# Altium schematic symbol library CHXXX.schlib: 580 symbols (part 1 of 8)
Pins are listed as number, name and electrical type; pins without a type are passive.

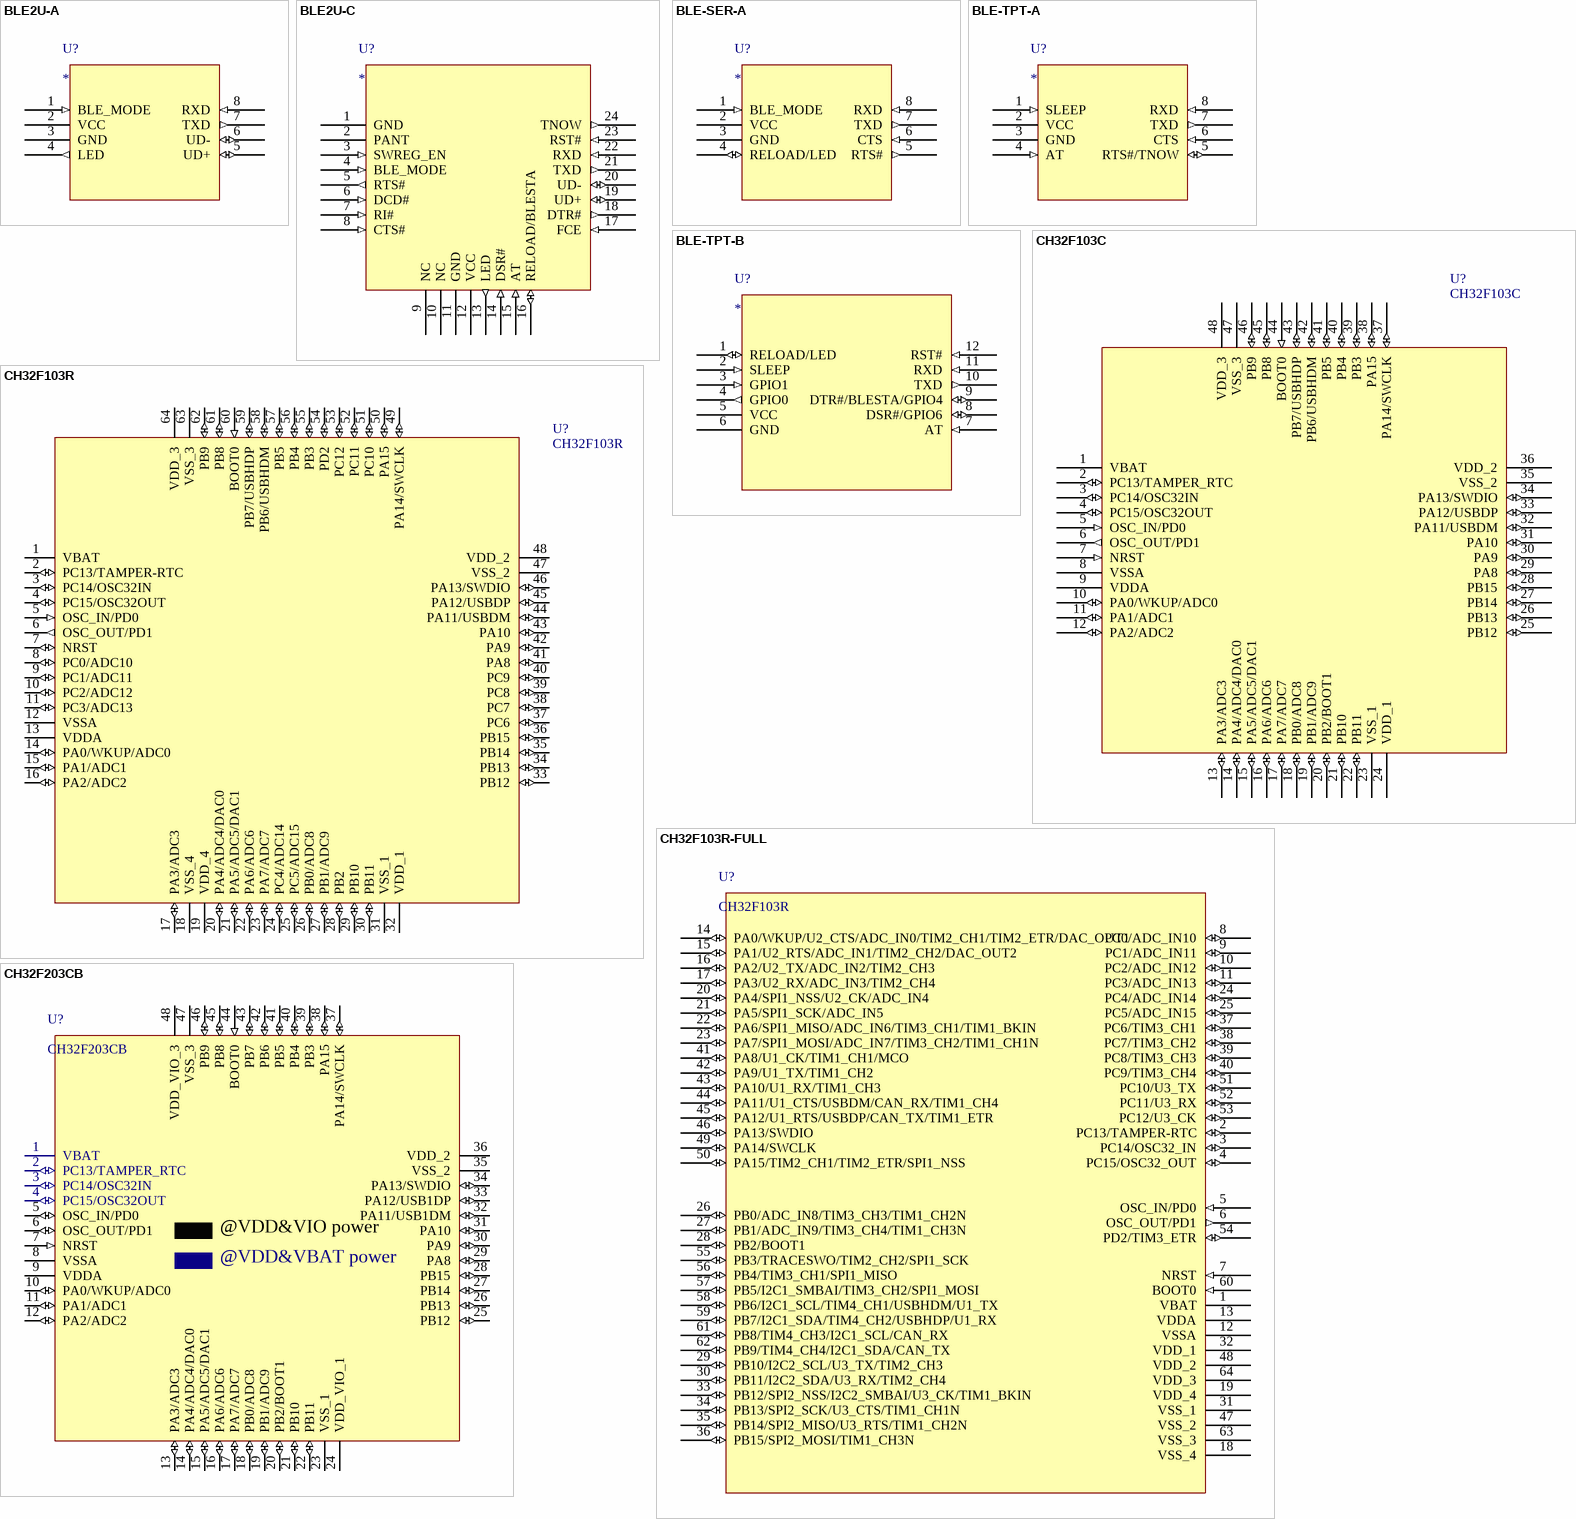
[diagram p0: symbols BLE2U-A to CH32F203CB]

## BLE2U-A
designator U?
BLE/UART/USB transparent transmission module, 8 pins
footprint BLEMOD-R1-1v1-8PIN
pins: 1 BLE_MODE (in), 2 VCC (power), 3 GND (power), 4 LED (out), 5 UD+ (io), 6 UD- (io), 7 TXD (out), 8 RXD (in)

## BLE2U-C
designator U?
BLE/UART/USB transparent transmission module, 24 pins
footprint BLEMOD-R2-1v0-24PIN
pins: 1 GND (power), 2 PANT, 3 SWREG_EN (in), 4 BLE_MODE (in), 5 RTS# (out), 6 DCD# (in), 7 RI# (in), 8 CTS# (in), 9 NC, 10 NC, 11 GND (power), 12 VCC (power), 13 LED (out), 14 DSR# (in), 15 AT (in), 16 RELOAD/BLESTA   (io), 17 FCE (in), 18 DTR# (out), 19 UD+ (io), 20 UD- (io), 21 TXD (out), 22 RXD (in), 23 RST# (in), 24 TNOW (out)

## BLE-SER-A
designator U?
BLE to UART / TTL Serial module, 8 pins
footprint BLEMOD-R1-1v1-8PIN
pins: 1 BLE_MODE (in), 2 VCC (power), 3 GND (power), 4 RELOAD/LED (io), 5 RTS# (out), 6 CTS (in), 7 TXD (out), 8 RXD (in)

## BLE-TPT-A
designator U?
BLE/UART transparent transmission module, 8 pins
footprint BLEMOD-R1-1v1-8PIN
pins: 1 SLEEP (in), 2 VCC (power), 3 GND (power), 4 AT (in), 5 RTS#/TNOW (io), 6 CTS (in), 7 TXD (out), 8 RXD (in)

## BLE-TPT-B
designator U?
BLE/UART transparent transmission module, 12 pins
footprint BLEMOD-R0-1v0-12PIN
pins: 1 RELOAD/LED (io), 2 SLEEP (in), 3 GPIO1 (in), 4 GPIO0 (out), 5 VCC (power), 6 GND (power), 7 AT (in), 8 DSR#/GPIO6 (io), 9 DTR#/BLESTA/GPIO4 (io), 10 TXD (out), 11 RXD (in), 12 RST# (in)

## CH32F103C
designator U?
ARM M3 MCU with USB device & USB host & ADC & 12bit DAC & Touch Key & CAN
footprint LQFP48
footprint QFN48_7X7 (Footprint not found)
pins: 1 VBAT (power), 2 PC13/TAMPER_RTC (io), 3 PC14/OSC32IN (io), 4 PC15/OSC32OUT (io), 5 OSC_IN/PD0 (in), 6 OSC_OUT/PD1 (out), 7 NRST (in), 8 VSSA (power), 9 VDDA (power), 10 PA0/WKUP/ADC0 (io), 11 PA1/ADC1 (io), 12 PA2/ADC2 (io), 13 PA3/ADC3 (io), 14 PA4/ADC4/DAC0 (io), 15 PA5/ADC5/DAC1 (io), 16 PA6/ADC6 (io), 17 PA7/ADC7 (io), 18 PB0/ADC8 (io), 19 PB1/ADC9 (io), 20 PB2/BOOT1 (io), 21 PB10 (io), 22 PB11 (io), 23 VSS_1 (power), 24 VDD_1 (power), 25 PB12 (io), 26 PB13 (io), 27 PB14 (io), 28 PB15 (io), 29 PA8 (io), 30 PA9 (io), 31 PA10 (io), 32 PA11/USBDM (io), 33 PA12/USBDP (io), 34 PA13/SWDIO (io), 35 VSS_2 (power), 36 VDD_2 (power), 37 PA14/SWCLK (io), 38 PA15 (io), 39 PB3 (io), 40 PB4 (io), 41 PB5 (io), 42 PB6/USBHDM (io), 43 PB7/USBHDP (io), 44 BOOT0 (in), 45 PB8 (io), 46 PB9 (io), 47 VSS_3 (power), 48 VDD_3 (power)

## CH32F103R
designator U?
ARM M3 MCU with USB device & USB host & ADC & 12bit DAC & Touch Key & CAN
footprint LQFP64M_10X10
pins: 1 VBAT (power), 2 PC13/TAMPER-RTC (io), 3 PC14/OSC32IN (io), 4 PC15/OSC32OUT (io), 5 OSC_IN/PD0 (in), 6 OSC_OUT/PD1 (out), 7 NRST (io), 8 PC0/ADC10 (io), 9 PC1/ADC11 (io), 10 PC2/ADC12 (io), 11 PC3/ADC13 (io), 12 VSSA (power), 13 VDDA (power), 14 PA0/WKUP/ADC0 (io), 15 PA1/ADC1 (io), 16 PA2/ADC2 (io), 17 PA3/ADC3 (io), 18 VSS_4 (power), 19 VDD_4 (power), 20 PA4/ADC4/DAC0 (io), 21 PA5/ADC5/DAC1 (io), 22 PA6/ADC6 (io), 23 PA7/ADC7 (io), 24 PC4/ADC14 (io), 25 PC5/ADC15 (io), 26 PB0/ADC8 (io), 27 PB1/ADC9 (io), 28 PB2 (io), 29 PB10 (io), 30 PB11 (io), 31 VSS_1 (power), 32 VDD_1 (power), 33 PB12 (io), 34 PB13 (io), 35 PB14 (io), 36 PB15 (io), 37 PC6 (io), 38 PC7 (io), 39 PC8 (io), 40 PC9 (io), 41 PA8 (io), 42 PA9 (io), 43 PA10 (io), 44 PA11/USBDM (io), 45 PA12/USBDP (io), 46 PA13/SWDIO (io), 47 VSS_2 (power), 48 VDD_2 (power), 49 PA14/SWCLK (io), 50 PA15 (io), 51 PC10 (io), 52 PC11 (io), 53 PC12 (io), 54 PD2 (io), 55 PB3 (io), 56 PB4 (io), 57 PB5 (io), 58 PB6/USBHDM (io), 59 PB7/USBHDP (io), 60 BOOT0 (in), 61 PB8 (io), 62 PB9 (io), 63 VSS_3 (power), 64 VDD_3 (power)

## CH32F103R-FULL
designator U?, comment CH32F103R
ARM M3 MCU with USB device & USB host & ADC & 12bit DAC & Touch Key & CAN
footprint LQFP64M_10X10 (Footprint not found)
pins: 1 VBAT (power), 2 PC13/TAMPER-RTC (io), 3 PC14/OSC32_IN (io), 4 PC15/OSC32_OUT (io), 5 OSC_IN/PD0 (in), 6 OSC_OUT/PD1 (out), 7 NRST (in), 8 PC0/ADC_IN10 (io), 9 PC1/ADC_IN11 (io), 10 PC2/ADC_IN12 (io), 11 PC3/ADC_IN13 (io), 12 VSSA (power), 13 VDDA (power), 14 PA0/WKUP/U2_CTS/ADC_IN0/TIM2_CH1/TIM2_ETR/DAC_OUT1 (io), 15 PA1/U2_RTS/ADC_IN1/TIM2_CH2/DAC_OUT2 (io), 16 PA2/U2_TX/ADC_IN2/TIM2_CH3 (io), 17 PA3/U2_RX/ADC_IN3/TIM2_CH4 (io), 18 VSS_4 (power), 19 VDD_4 (power), 20 PA4/SPI1_NSS/U2_CK/ADC_IN4 (io), 21 PA5/SPI1_SCK/ADC_IN5 (io), 22 PA6/SPI1_MISO/ADC_IN6/TIM3_CH1/TIM1_BKIN (io), 23 PA7/SPI1_MOSI/ADC_IN7/TIM3_CH2/TIM1_CH1N (io), 24 PC4/ADC_IN14 (io), 25 PC5/ADC_IN15 (io), 26 PB0/ADC_IN8/TIM3_CH3/TIM1_CH2N (io), 27 PB1/ADC_IN9/TIM3_CH4/TIM1_CH3N (io), 28 PB2/BOOT1 (io), 29 PB10/I2C2_SCL/U3_TX/TIM2_CH3 (io), 30 PB11/I2C2_SDA/U3_RX/TIM2_CH4 (io), 31 VSS_1 (power), 32 VDD_1 (power), 33 PB12/SPI2_NSS/I2C2_SMBAI/U3_CK/TIM1_BKIN (io), 34 PB13/SPI2_SCK/U3_CTS/TIM1_CH1N  (io), 35 PB14/SPI2_MISO/U3_RTS/TIM1_CH2N (io), 36 PB15/SPI2_MOSI/TIM1_CH3N (io), 37 PC6/TIM3_CH1 (io), 38 PC7/TIM3_CH2 (io), 39 PC8/TIM3_CH3 (io), 40 PC9/TIM3_CH4 (io), 41 PA8/U1_CK/TIM1_CH1/MCO (io), 42 PA9/U1_TX/TIM1_CH2 (io), 43 PA10/U1_RX/TIM1_CH3 (io), 44 PA11/U1_CTS/USBDM/CAN_RX/TIM1_CH4 (io), 45 PA12/U1_RTS/USBDP/CAN_TX/TIM1_ETR (io), 46 PA13/SWDIO (io), 47 VSS_2 (power), 48 VDD_2 (power), 49 PA14/SWCLK (io), 50 PA15/TIM2_CH1/TIM2_ETR/SPI1_NSS (io), 51 PC10/U3_TX (io), 52 PC11/U3_RX (io), 53 PC12/U3_CK (io), 54 PD2/TIM3_ETR (io), 55 PB3/TRACESWO/TIM2_CH2/SPI1_SCK (io), 56 PB4/TIM3_CH1/SPI1_MISO (io), 57 PB5/I2C1_SMBAI/TIM3_CH2/SPI1_MOSI (io), 58 PB6/I2C1_SCL/TIM4_CH1/USBHDM/U1_TX (io), 59 PB7/I2C1_SDA/TIM4_CH2/USBHDP/U1_RX (io), 60 BOOT0 (in), 61 PB8/TIM4_CH3/I2C1_SCL/CAN_RX (io), 62 PB9/TIM4_CH4/I2C1_SDA/CAN_TX (io), 63 VSS_3 (power), 64 VDD_3 (power)

## CH32F203CB
designator U?
ARM M3 HD-MCU, 144MHz, 8*UART, 10*Timer, 4*OPA
footprint LQFP48
pins: 1 VBAT (power), 2 PC13/TAMPER_RTC (io), 3 PC14/OSC32IN (io), 4 PC15/OSC32OUT (io), 5 OSC_IN/PD0 (io), 6 OSC_OUT/PD1 (io), 7 NRST (in), 8 VSSA (power), 9 VDDA (power), 10 PA0/WKUP/ADC0 (io), 11 PA1/ADC1 (io), 12 PA2/ADC2 (io), 13 PA3/ADC3 (io), 14 PA4/ADC4/DAC0 (io), 15 PA5/ADC5/DAC1 (io), 16 PA6/ADC6 (io), 17 PA7/ADC7 (io), 18 PB0/ADC8 (io), 19 PB1/ADC9 (io), 20 PB2/BOOT1 (io), 21 PB10 (io), 22 PB11 (io), 23 VSS_1 (power), 24 VDD_VIO_1 (power), 25 PB12 (io), 26 PB13 (io), 27 PB14 (io), 28 PB15 (io), 29 PA8 (io), 30 PA9 (io), 31 PA10 (io), 32 PA11/USB1DM (io), 33 PA12/USB1DP (io), 34 PA13/SWDIO (io), 35 VSS_2 (power), 36 VDD_2 (power), 37 PA14/SWCLK (io), 38 PA15 (io), 39 PB3 (io), 40 PB4 (io), 41 PB5 (io), 42 PB6 (io), 43 PB7 (io), 44 BOOT0 (in), 45 PB8 (io), 46 PB9 (io), 47 VSS_3 (power), 48 VDD_VIO_3 (power)

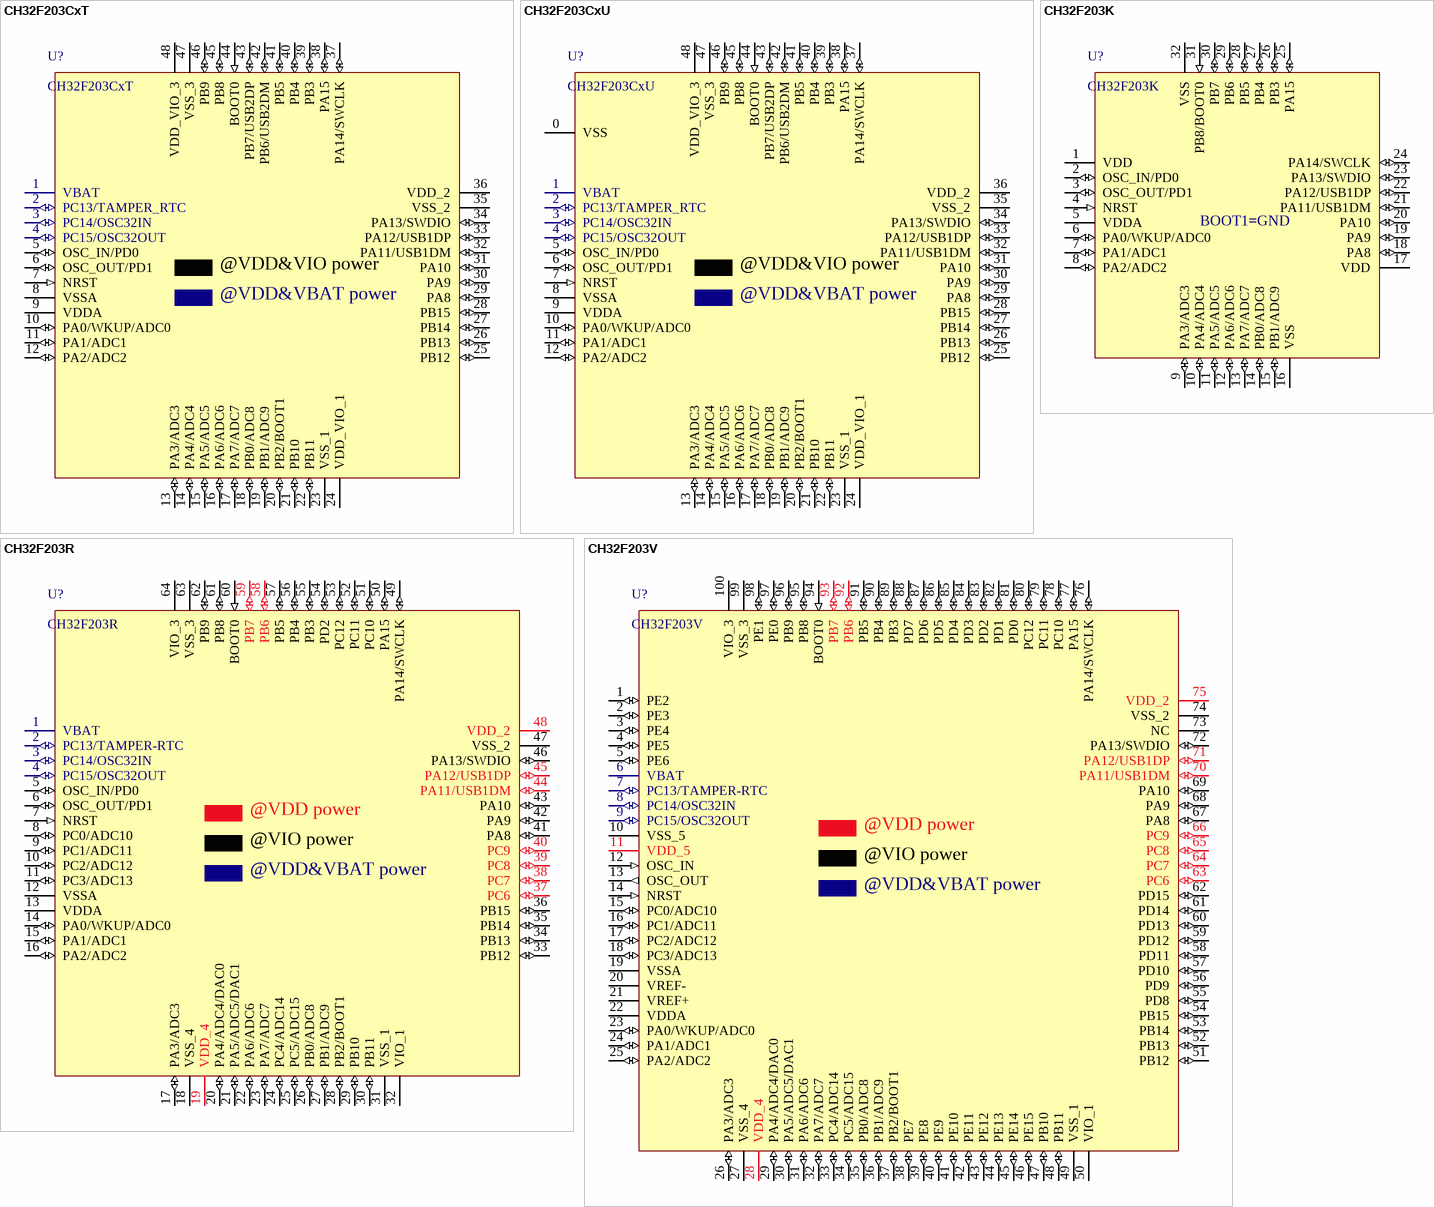
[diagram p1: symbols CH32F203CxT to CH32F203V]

## CH32F203CxT
designator U?
ARM M3 LMD-MCU, 144MHz, 2*USB FS, CAN
footprint LQFP48
pins: 1 VBAT (power), 2 PC13/TAMPER_RTC (io), 3 PC14/OSC32IN (io), 4 PC15/OSC32OUT (io), 5 OSC_IN/PD0 (io), 6 OSC_OUT/PD1 (io), 7 NRST (in), 8 VSSA (power), 9 VDDA (power), 10 PA0/WKUP/ADC0 (io), 11 PA1/ADC1 (io), 12 PA2/ADC2 (io), 13 PA3/ADC3 (io), 14 PA4/ADC4 (io), 15 PA5/ADC5 (io), 16 PA6/ADC6 (io), 17 PA7/ADC7 (io), 18 PB0/ADC8 (io), 19 PB1/ADC9 (io), 20 PB2/BOOT1 (io), 21 PB10 (io), 22 PB11 (io), 23 VSS_1 (power), 24 VDD_VIO_1 (power), 25 PB12 (io), 26 PB13 (io), 27 PB14 (io), 28 PB15 (io), 29 PA8 (io), 30 PA9 (io), 31 PA10 (io), 32 PA11/USB1DM (io), 33 PA12/USB1DP (io), 34 PA13/SWDIO (io), 35 VSS_2 (power), 36 VDD_2 (power), 37 PA14/SWCLK (io), 38 PA15 (io), 39 PB3 (io), 40 PB4 (io), 41 PB5 (io), 42 PB6/USB2DM (io), 43 PB7/USB2DP (io), 44 BOOT0 (in), 45 PB8 (io), 46 PB9 (io), 47 VSS_3 (power), 48 VDD_VIO_3 (power)

## CH32F203CxU
designator U?
ARM M3 LMD-MCU, 144MHz, 2*USB FS, CAN
footprint QFN48_7X7 (Footprint not found)
pins: 0 VSS (power), 1 VBAT (power), 2 PC13/TAMPER_RTC (io), 3 PC14/OSC32IN (io), 4 PC15/OSC32OUT (io), 5 OSC_IN/PD0 (io), 6 OSC_OUT/PD1 (io), 7 NRST (in), 8 VSSA (power), 9 VDDA (power), 10 PA0/WKUP/ADC0 (io), 11 PA1/ADC1 (io), 12 PA2/ADC2 (io), 13 PA3/ADC3 (io), 14 PA4/ADC4 (io), 15 PA5/ADC5 (io), 16 PA6/ADC6 (io), 17 PA7/ADC7 (io), 18 PB0/ADC8 (io), 19 PB1/ADC9 (io), 20 PB2/BOOT1 (io), 21 PB10 (io), 22 PB11 (io), 23 VSS_1 (power), 24 VDD_VIO_1 (power), 25 PB12 (io), 26 PB13 (io), 27 PB14 (io), 28 PB15 (io), 29 PA8 (io), 30 PA9 (io), 31 PA10 (io), 32 PA11/USB1DM (io), 33 PA12/USB1DP (io), 34 PA13/SWDIO (io), 35 VSS_2 (power), 36 VDD_2 (power), 37 PA14/SWCLK (io), 38 PA15 (io), 39 PB3 (io), 40 PB4 (io), 41 PB5 (io), 42 PB6/USB2DM (io), 43 PB7/USB2DP (io), 44 BOOT0 (in), 45 PB8 (io), 46 PB9 (io), 47 VSS_3 (power), 48 VDD_VIO_3 (power)

## CH32F203K
designator U?
ARM M3 LMD-MCU, 144MHz, USB FS, CAN
footprint LQFP32
pins: 1 VDD (power), 2 OSC_IN/PD0 (io), 3 OSC_OUT/PD1 (io), 4 NRST (in), 5 VDDA (power), 6 PA0/WKUP/ADC0 (io), 7 PA1/ADC1 (io), 8 PA2/ADC2 (io), 9 PA3/ADC3 (io), 10 PA4/ADC4 (io), 11 PA5/ADC5 (io), 12 PA6/ADC6 (io), 13 PA7/ADC7 (io), 14 PB0/ADC8 (io), 15 PB1/ADC9 (io), 16 VSS (power), 17 VDD (power), 18 PA8 (io), 19 PA9 (io), 20 PA10 (io), 21 PA11/USB1DM (io), 22 PA12/USB1DP (io), 23 PA13/SWDIO (io), 24 PA14/SWCLK (io), 25 PA15 (io), 26 PB3 (io), 27 PB4 (io), 28 PB5 (io), 29 PB6 (io), 30 PB7 (io), 31 PB8/BOOT0 (in), 32 VSS (power)

## CH32F203R
designator U?
ARM M3 HD-MCU, 144MHz, 8*UART, 10*Timer, 4*OPA
footprint LQFP64M_10X10
pins: 1 VBAT (power), 2 PC13/TAMPER-RTC (io), 3 PC14/OSC32IN (io), 4 PC15/OSC32OUT (io), 5 OSC_IN/PD0 (io), 6 OSC_OUT/PD1 (io), 7 NRST (in), 8 PC0/ADC10 (io), 9 PC1/ADC11 (io), 10 PC2/ADC12 (io), 11 PC3/ADC13 (io), 12 VSSA (power), 13 VDDA (power), 14 PA0/WKUP/ADC0 (io), 15 PA1/ADC1 (io), 16 PA2/ADC2 (io), 17 PA3/ADC3 (io), 18 VSS_4 (power), 19 VDD_4 (power), 20 PA4/ADC4/DAC0 (io), 21 PA5/ADC5/DAC1 (io), 22 PA6/ADC6 (io), 23 PA7/ADC7 (io), 24 PC4/ADC14 (io), 25 PC5/ADC15 (io), 26 PB0/ADC8 (io), 27 PB1/ADC9 (io), 28 PB2/BOOT1 (io), 29 PB10 (io), 30 PB11 (io), 31 VSS_1 (power), 32 VIO_1 (power), 33 PB12 (io), 34 PB13 (io), 35 PB14 (io), 36 PB15 (io), 37 PC6 (io), 38 PC7 (io), 39 PC8 (io), 40 PC9 (io), 41 PA8 (io), 42 PA9 (io), 43 PA10 (io), 44 PA11/USB1DM (io), 45 PA12/USB1DP (io), 46 PA13/SWDIO (io), 47 VSS_2 (power), 48 VDD_2 (power), 49 PA14/SWCLK (io), 50 PA15 (io), 51 PC10 (io), 52 PC11 (io), 53 PC12 (io), 54 PD2 (io), 55 PB3 (io), 56 PB4 (io), 57 PB5 (io), 58 PB6 (io), 59 PB7 (io), 60 BOOT0 (in), 61 PB8 (io), 62 PB9 (io), 63 VSS_3 (power), 64 VIO_3 (power)

## CH32F203V
designator U?
ARM M3 HD-MCU, 144MHz, 8*UART, 10*Timer, 4*OPA
footprint LQFP100
pins: 1 PE2 (io), 2 PE3 (io), 3 PE4 (io), 4 PE5 (io), 5 PE6 (io), 6 VBAT (power), 7 PC13/TAMPER-RTC (io), 8 PC14/OSC32IN (io), 9 PC15/OSC32OUT (io), 10 VSS_5 (power), 11 VDD_5 (power), 12 OSC_IN (in), 13 OSC_OUT (out), 14 NRST (in), 15 PC0/ADC10 (io), 16 PC1/ADC11 (io), 17 PC2/ADC12 (io), 18 PC3/ADC13 (io), 19 VSSA (power), 20 VREF- (power), 21 VREF+ (power), 22 VDDA (power), 23 PA0/WKUP/ADC0 (io), 24 PA1/ADC1 (io), 25 PA2/ADC2 (io), 26 PA3/ADC3 (io), 27 VSS_4 (power), 28 VDD_4 (power), 29 PA4/ADC4/DAC0 (io), 30 PA5/ADC5/DAC1 (io), 31 PA6/ADC6 (io), 32 PA7/ADC7 (io), 33 PC4/ADC14 (io), 34 PC5/ADC15 (io), 35 PB0/ADC8 (io), 36 PB1/ADC9 (io), 37 PB2/BOOT1 (io), 38 PE7 (io), 39 PE8 (io), 40 PE9 (io), 41 PE10 (io), 42 PE11 (io), 43 PE12 (io), 44 PE13 (io), 45 PE14 (io), 46 PE15 (io), 47 PB10 (io), 48 PB11 (io), 49 VSS_1 (power), 50 VIO_1 (power), 51 PB12 (io), 52 PB13 (io), 53 PB14 (io), 54 PB15 (io), 55 PD8 (io), 56 PD9 (io), 57 PD10 (io), 58 PD11 (io), 59 PD12 (io), 60 PD13 (io), 61 PD14 (io), 62 PD15 (io), 63 PC6 (io), 64 PC7 (io), 65 PC8 (io), 66 PC9 (io), 67 PA8 (io), 68 PA9 (io), 69 PA10 (io), 70 PA11/USB1DM (io), 71 PA12/USB1DP (io), 72 PA13/SWDIO (io), 73 NC (hiz), 74 VSS_2 (power), 75 VDD_2 (power), 76 PA14/SWCLK (io), 77 PA15 (io), 78 PC10 (io), 79 PC11 (io), 80 PC12 (io), 81 PD0 (io), 82 PD1 (io), 83 PD2 (io), 84 PD3 (io), 85 PD4 (io), 86 PD5 (io), 87 PD6 (io), 88 PD7 (io), 89 PB3 (io), 90 PB4 (io), 91 PB5 (io), 92 PB6 (io), 93 PB7 (io), 94 BOOT0 (in), 95 PB8 (io), 96 PB9 (io), 97 PE0 (io), 98 PE1 (io), 99 VSS_3 (power), 100 VIO_3 (power)

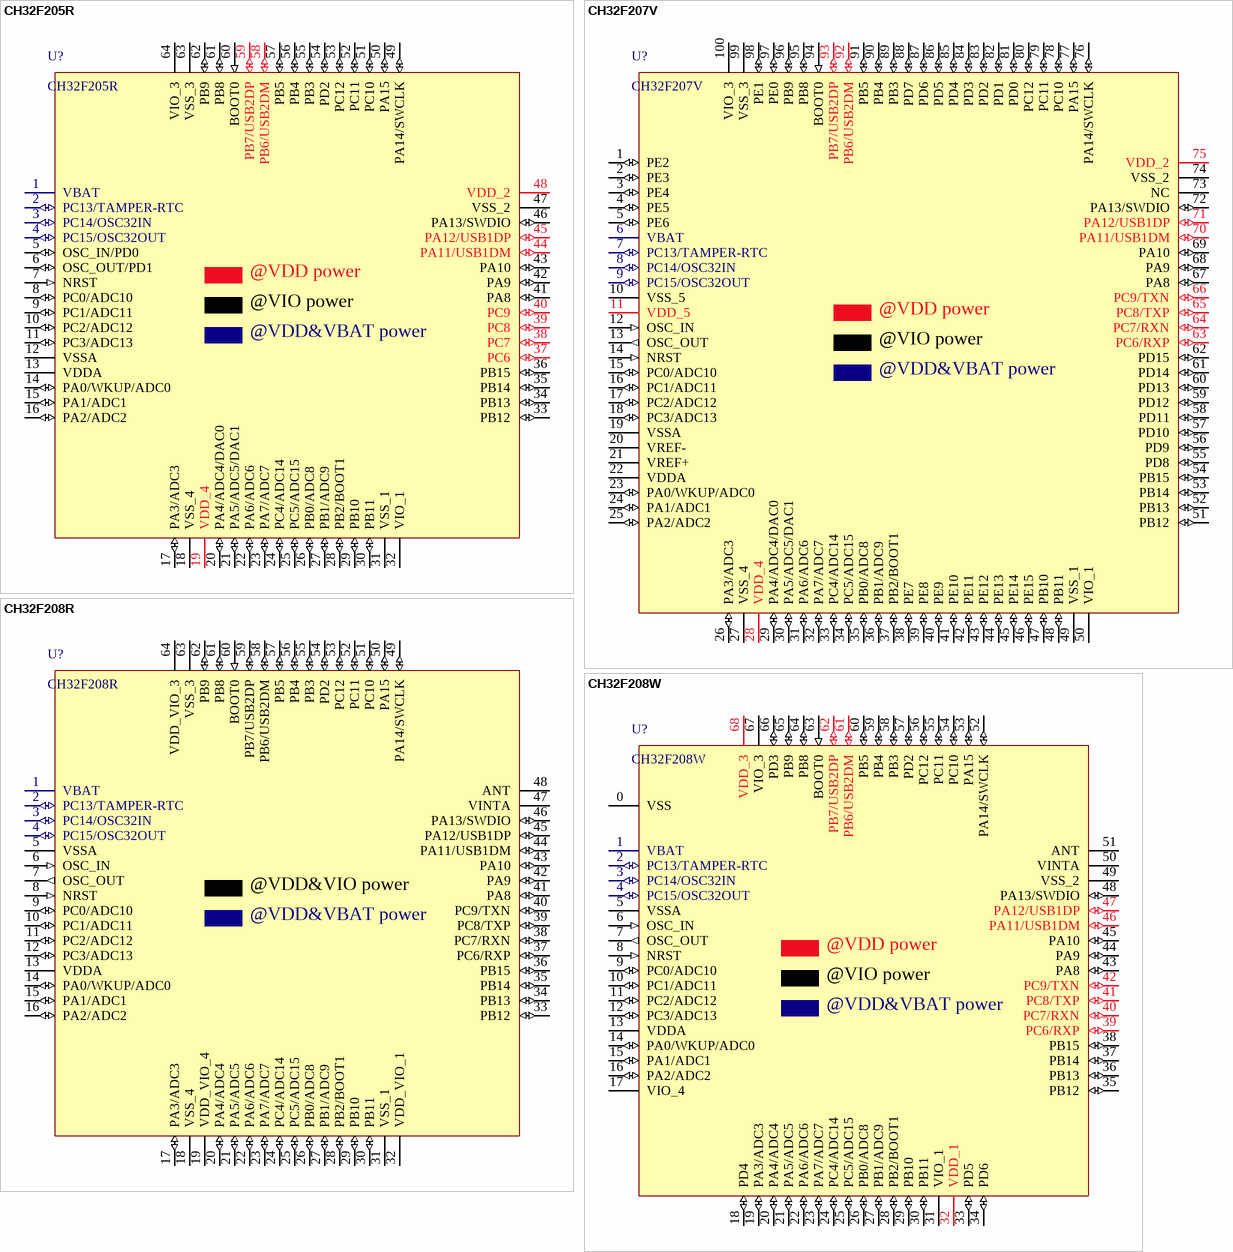
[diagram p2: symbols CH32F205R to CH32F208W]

## CH32F205R
designator U?
ARM M3 HD-MCU, 144MHz, USB_480M, USB OTG, 2*CAN, 4*OPA
footprint LQFP64M_10X10
pins: 1 VBAT (power), 2 PC13/TAMPER-RTC (io), 3 PC14/OSC32IN (io), 4 PC15/OSC32OUT (io), 5 OSC_IN/PD0 (io), 6 OSC_OUT/PD1 (io), 7 NRST (in), 8 PC0/ADC10 (io), 9 PC1/ADC11 (io), 10 PC2/ADC12 (io), 11 PC3/ADC13 (io), 12 VSSA (power), 13 VDDA (power), 14 PA0/WKUP/ADC0 (io), 15 PA1/ADC1 (io), 16 PA2/ADC2 (io), 17 PA3/ADC3 (io), 18 VSS_4 (power), 19 VDD_4 (power), 20 PA4/ADC4/DAC0 (io), 21 PA5/ADC5/DAC1 (io), 22 PA6/ADC6 (io), 23 PA7/ADC7 (io), 24 PC4/ADC14 (io), 25 PC5/ADC15 (io), 26 PB0/ADC8 (io), 27 PB1/ADC9 (io), 28 PB2/BOOT1 (io), 29 PB10 (io), 30 PB11 (io), 31 VSS_1 (power), 32 VIO_1 (power), 33 PB12 (io), 34 PB13 (io), 35 PB14 (io), 36 PB15 (io), 37 PC6 (io), 38 PC7 (io), 39 PC8 (io), 40 PC9 (io), 41 PA8 (io), 42 PA9 (io), 43 PA10 (io), 44 PA11/USB1DM (io), 45 PA12/USB1DP (io), 46 PA13/SWDIO (io), 47 VSS_2 (power), 48 VDD_2 (power), 49 PA14/SWCLK (io), 50 PA15 (io), 51 PC10 (io), 52 PC11 (io), 53 PC12 (io), 54 PD2 (io), 55 PB3 (io), 56 PB4 (io), 57 PB5 (io), 58 PB6/USB2DM (io), 59 PB7/USB2DP (io), 60 BOOT0 (in), 61 PB8 (io), 62 PB9 (io), 63 VSS_3 (power), 64 VIO_3 (power)

## CH32F207V
designator U?
ARM M3 HD-MCU, 144MHz, USB_480M, USB OTG, 1000M Ethernet MAC, 2*CAN
footprint LQFP100
pins: 1 PE2 (io), 2 PE3 (io), 3 PE4 (io), 4 PE5 (io), 5 PE6 (io), 6 VBAT (power), 7 PC13/TAMPER-RTC (io), 8 PC14/OSC32IN (io), 9 PC15/OSC32OUT (io), 10 VSS_5 (power), 11 VDD_5 (power), 12 OSC_IN (in), 13 OSC_OUT (out), 14 NRST (in), 15 PC0/ADC10 (io), 16 PC1/ADC11 (io), 17 PC2/ADC12 (io), 18 PC3/ADC13 (io), 19 VSSA (power), 20 VREF- (power), 21 VREF+ (power), 22 VDDA (power), 23 PA0/WKUP/ADC0 (io), 24 PA1/ADC1 (io), 25 PA2/ADC2 (io), 26 PA3/ADC3 (io), 27 VSS_4 (power), 28 VDD_4 (power), 29 PA4/ADC4/DAC0 (io), 30 PA5/ADC5/DAC1 (io), 31 PA6/ADC6 (io), 32 PA7/ADC7 (io), 33 PC4/ADC14 (io), 34 PC5/ADC15 (io), 35 PB0/ADC8 (io), 36 PB1/ADC9 (io), 37 PB2/BOOT1 (io), 38 PE7 (io), 39 PE8 (io), 40 PE9 (io), 41 PE10 (io), 42 PE11 (io), 43 PE12 (io), 44 PE13 (io), 45 PE14 (io), 46 PE15 (io), 47 PB10 (io), 48 PB11 (io), 49 VSS_1 (power), 50 VIO_1 (power), 51 PB12 (io), 52 PB13 (io), 53 PB14 (io), 54 PB15 (io), 55 PD8 (io), 56 PD9 (io), 57 PD10 (io), 58 PD11 (io), 59 PD12 (io), 60 PD13 (io), 61 PD14 (io), 62 PD15 (io), 63 PC6/RXP (io), 64 PC7/RXN (io), 65 PC8/TXP (io), 66 PC9/TXN (io), 67 PA8 (io), 68 PA9 (io), 69 PA10 (io), 70 PA11/USB1DM (io), 71 PA12/USB1DP (io), 72 PA13/SWDIO (io), 73 NC (hiz), 74 VSS_2 (power), 75 VDD_2 (power), 76 PA14/SWCLK (io), 77 PA15 (io), 78 PC10 (io), 79 PC11 (io), 80 PC12 (io), 81 PD0 (io), 82 PD1 (io), 83 PD2 (io), 84 PD3 (io), 85 PD4 (io), 86 PD5 (io), 87 PD6 (io), 88 PD7 (io), 89 PB3 (io), 90 PB4 (io), 91 PB5 (io), 92 PB6/USB2DM (io), 93 PB7/USB2DP (io), 94 BOOT0 (in), 95 PB8 (io), 96 PB9 (io), 97 PE0 (io), 98 PE1 (io), 99 VSS_3 (power), 100 VIO_3 (power)

## CH32F208R
designator U?
ARM M3 BLE5.3 MCU, 10M Ethernet, 2*USB, CAN
footprint LQFP64M_10X10
pins: 1 VBAT (power), 2 PC13/TAMPER-RTC (io), 3 PC14/OSC32IN (io), 4 PC15/OSC32OUT (io), 5 VSSA (power), 6 OSC_IN (in), 7 OSC_OUT (out), 8 NRST (in), 9 PC0/ADC10 (io), 10 PC1/ADC11 (io), 11 PC2/ADC12 (io), 12 PC3/ADC13 (io), 13 VDDA (power), 14 PA0/WKUP/ADC0 (io), 15 PA1/ADC1 (io), 16 PA2/ADC2 (io), 17 PA3/ADC3 (io), 18 VSS_4 (power), 19 VDD_VIO_4 (power), 20 PA4/ADC4 (io), 21 PA5/ADC5 (io), 22 PA6/ADC6 (io), 23 PA7/ADC7 (io), 24 PC4/ADC14 (io), 25 PC5/ADC15 (io), 26 PB0/ADC8 (io), 27 PB1/ADC9 (io), 28 PB2/BOOT1 (io), 29 PB10 (io), 30 PB11 (io), 31 VSS_1 (power), 32 VDD_VIO_1 (power), 33 PB12 (io), 34 PB13 (io), 35 PB14 (io), 36 PB15 (io), 37 PC6/RXP (io), 38 PC7/RXN (io), 39 PC8/TXP (io), 40 PC9/TXN (io), 41 PA8 (io), 42 PA9 (io), 43 PA10 (io), 44 PA11/USB1DM (io), 45 PA12/USB1DP (io), 46 PA13/SWDIO (io), 47 VINTA (power), 48 ANT (power), 49 PA14/SWCLK (io), 50 PA15 (io), 51 PC10 (io), 52 PC11 (io), 53 PC12 (io), 54 PD2 (io), 55 PB3 (io), 56 PB4 (io), 57 PB5 (io), 58 PB6/USB2DM (io), 59 PB7/USB2DP (io), 60 BOOT0 (in), 61 PB8 (io), 62 PB9 (io), 63 VSS_3 (power), 64 VDD_VIO_3 (power)

## CH32F208W
designator U?
ARM M3 BLE5.3 MCU, 10M Ethernet, 2*USB, CAN
footprint QFN68_8X8
pins: 0 VSS (power), 1 VBAT (power), 2 PC13/TAMPER-RTC (io), 3 PC14/OSC32IN (io), 4 PC15/OSC32OUT (io), 5 VSSA (power), 6 OSC_IN (in), 7 OSC_OUT (out), 8 NRST (in), 9 PC0/ADC10 (io), 10 PC1/ADC11 (io), 11 PC2/ADC12 (io), 12 PC3/ADC13 (io), 13 VDDA (power), 14 PA0/WKUP/ADC0 (io), 15 PA1/ADC1 (io), 16 PA2/ADC2 (io), 17 VIO_4 (power), 18 PD4 (io), 19 PA3/ADC3 (io), 20 PA4/ADC4 (io), 21 PA5/ADC5 (io), 22 PA6/ADC6 (io), 23 PA7/ADC7 (io), 24 PC4/ADC14 (io), 25 PC5/ADC15 (io), 26 PB0/ADC8 (io), 27 PB1/ADC9 (io), 28 PB2/BOOT1 (io), 29 PB10 (io), 30 PB11 (io), 31 VIO_1 (power), 32 VDD_1 (power), 33 PD5 (io), 34 PD6 (io), 35 PB12 (io), 36 PB13 (io), 37 PB14 (io), 38 PB15 (io), 39 PC6/RXP (io), 40 PC7/RXN (io), 41 PC8/TXP (io), 42 PC9/TXN (io), 43 PA8 (io), 44 PA9 (io), 45 PA10 (io), 46 PA11/USB1DM (io), 47 PA12/USB1DP (io), 48 PA13/SWDIO (io), 49 VSS_2 (power), 50 VINTA (power), 51 ANT (power), 52 PA14/SWCLK (io), 53 PA15 (io), 54 PC10 (io), 55 PC11 (io), 56 PC12 (io), 57 PD2 (io), 58 PB3 (io), 59 PB4 (io), 60 PB5 (io), 61 PB6/USB2DM (io), 62 PB7/USB2DP (io), 63 BOOT0 (in), 64 PB8 (io), 65 PB9 (io), 66 PD3 (io), 67 VIO_3 (power), 68 VDD_3 (power)

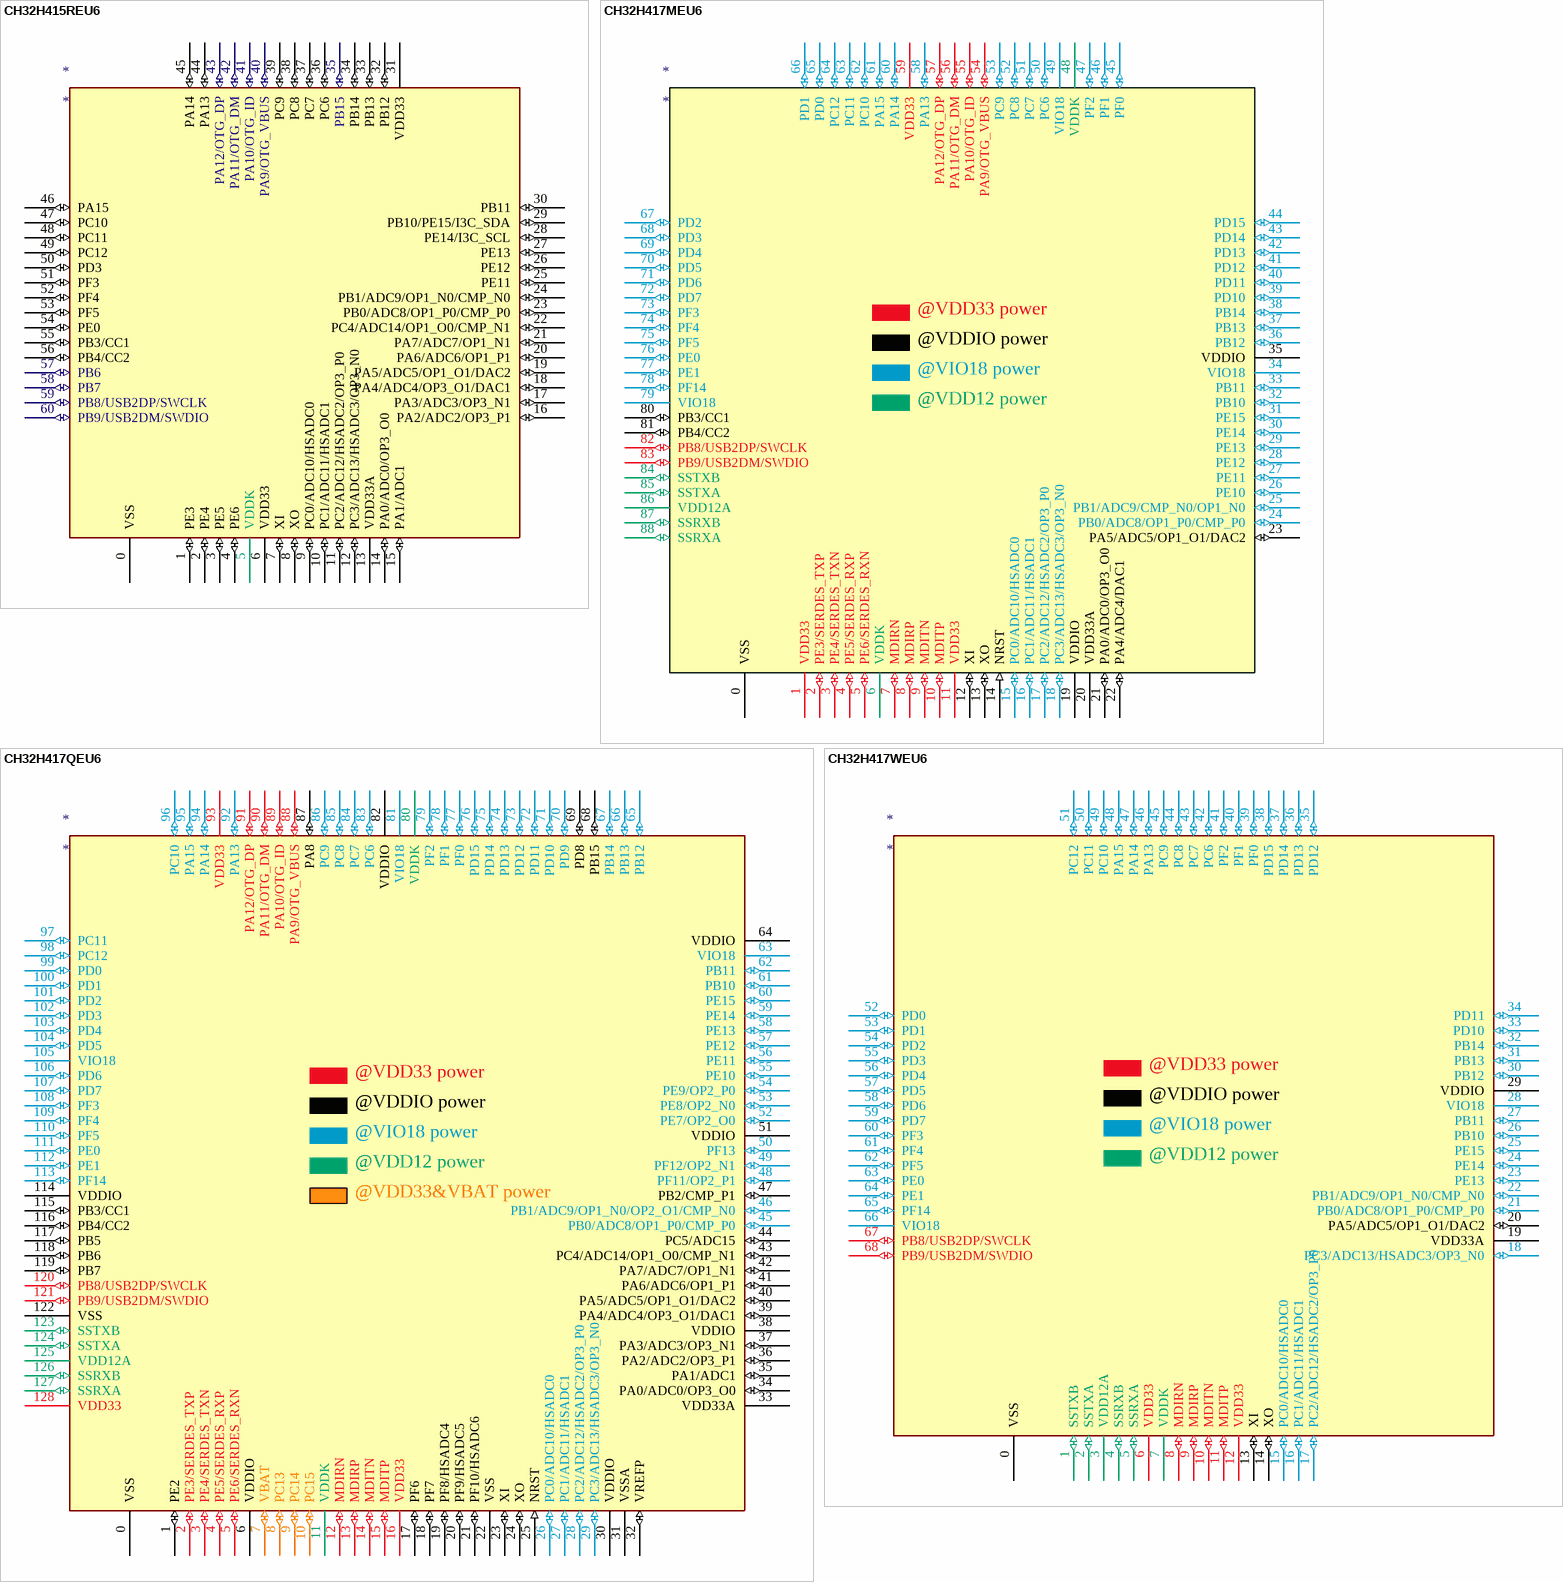
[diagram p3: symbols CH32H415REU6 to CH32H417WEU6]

## CH32H415REU6
designator *
RISC-V FPU HD-MCU, 400MHz, USB2.0 & PD, OPA, ADC, DAC
footprint QFN60_6X6 (Footprint not found)
pins: 0 VSS (power), 1 PE3 (io), 2 PE4 (io), 3 PE5 (io), 4 PE6 (io), 5 VDDK (power), 6 VDD33 (power), 7 XI (io), 8 XO (io), 9 PC0/ADC10/HSADC0 (io), 10 PC1/ADC11/HSADC1 (io), 11 PC2/ADC12/HSADC2/OP3_P0 (io), 12 PC3/ADC13/HSADC3/OP3_N0 (io), 13 VDD33A (power), 14 PA0/ADC0/OP3_O0 (io), 15 PA1/ADC1 (io), 16 PA2/ADC2/OP3_P1 (io), 17 PA3/ADC3/OP3_N1 (io), 18 PA4/ADC4/OP3_O1/DAC1 (io), 19 PA5/ADC5/OP1_O1/DAC2 (io), 20 PA6/ADC6/OP1_P1 (io), 21 PA7/ADC7/OP1_N1 (io), 22 PC4/ADC14/OP1_O0/CMP_N1 (io), 23 PB0/ADC8/OP1_P0/CMP_P0 (io), 24 PB1/ADC9/OP1_N0/CMP_N0 (io), 25 PE11 (io), 26 PE12 (io), 27 PE13 (io), 28 PE14/I3C_SCL (io), 29 PB10/PE15/I3C_SDA (io), 30 PB11 (io), 31 VDD33 (power), 32 PB12 (io), 33 PB13 (io), 34 PB14 (io), 35 PB15 (io), 36 PC6 (io), 37 PC7 (io), 38 PC8 (io), 39 PC9 (io), 40 PA9/OTG_VBUS (io), 41 PA10/OTG_ID (io), 42 PA11/OTG_DM (io), 43 PA12/OTG_DP (io), 44 PA13 (io), 45 PA14 (io), 46 PA15 (io), 47 PC10 (io), 48 PC11 (io), 49 PC12 (io), 50 PD3 (io), 51 PF3 (io), 52 PF4 (io), 53 PF5 (io), 54 PE0 (io), 55 PB3/CC1 (io), 56 PB4/CC2 (io), 57 PB6 (io), 58 PB7 (io), 59 PB8/USB2DP/SWCLK (io), 60 PB9/USB2DM/SWDIO (io)

## CH32H417MEU6
designator *
RISC-V FPU HD-MCU, 400MHz, USB3.0 & PD, 100M Ethernet, DVP, SDMMC, QSPI, OPA, ADC, DAC
footprint QFN88_10X10 (Footprint not found)
pins: 0 VSS (power), 1 VDD33 (power), 2 PE3/SERDES_TXP (io), 3 PE4/SERDES_TXN (io), 4 PE5/SERDES_RXP (io), 5 PE6/SERDES_RXN (io), 6 VDDK (power), 7 MDIRN (io), 8 MDIRP (io), 9 MDITN (io), 10 MDITP (io), 11 VDD33 (power), 12 XI (io), 13 XO (io), 14 NRST (in), 15 PC0/ADC10/HSADC0 (io), 16 PC1/ADC11/HSADC1 (io), 17 PC2/ADC12/HSADC2/OP3_P0 (io), 18 PC3/ADC13/HSADC3/OP3_N0 (io), 19 VDDIO (power), 20 VDD33A (power), 21 PA0/ADC0/OP3_O0 (io), 22 PA4/ADC4/DAC1 (io), 23 PA5/ADC5/OP1_O1/DAC2 (io), 24 PB0/ADC8/OP1_P0/CMP_P0 (io), 25 PB1/ADC9/CMP_N0/OP1_N0 (io), 26 PE10 (io), 27 PE11 (io), 28 PE12 (io), 29 PE13 (io), 30 PE14 (io), 31 PE15 (io), 32 PB10 (io), 33 PB11 (io), 34 VIO18 (power), 35 VDDIO (power), 36 PB12 (io), 37 PB13 (io), 38 PB14 (io), 39 PD10 (io), 40 PD11 (io), 41 PD12 (io), 42 PD13 (io), 43 PD14 (io), 44 PD15 (io), 45 PF0 (io), 46 PF1 (io), 47 PF2 (io), 48 VDDK (power), 49 VIO18 (power), 50 PC6 (io), 51 PC7 (io), 52 PC8 (io), 53 PC9 (io), 54 PA9/OTG_VBUS (io), 55 PA10/OTG_ID (io), 56 PA11/OTG_DM (io), 57 PA12/OTG_DP (io), 58 PA13 (io), 59 VDD33 (power), 60 PA14 (io), 61 PA15 (io), 62 PC10 (io), 63 PC11 (io), 64 PC12 (io), 65 PD0 (io), 66 PD1 (io), 67 PD2 (io), 68 PD3 (io), 69 PD4 (io), 70 PD5 (io), 71 PD6 (io), 72 PD7 (io), 73 PF3 (io), 74 PF4 (io), 75 PF5 (io), 76 PE0 (io), 77 PE1 (io), 78 PF14 (io), 79 VIO18 (power), 80 PB3/CC1 (io), 81 PB4/CC2 (io), 82 PB8/USB2DP/SWCLK (io), 83 PB9/USB2DM/SWDIO (io), 84 SSTXB (io), 85 SSTXA (io), 86 VDD12A (power), 87 SSRXB (io), 88 SSRXA (io)

## CH32H417QEU6
designator *
RISC-V FPU HD-MCU, 400MHz, USB3.0 & PD, 100M Ethernet, DVP, SDMMC, QSPI, OPA, ADC, DAC
footprint QFN128_12.3X12.3 (Footprint not found)
pins: 0 VSS (power), 1 PE2 (io), 2 PE3/SERDES_TXP (io), 3 PE4/SERDES_TXN (io), 4 PE5/SERDES_RXP (io), 5 PE6/SERDES_RXN (io), 6 VDDIO (power), 7 VBAT (io), 8 PC13 (io), 9 PC14 (io), 10 PC15 (io), 11 VDDK (power), 12 MDIRN (io), 13 MDIRP (io), 14 MDITN (io), 15 MDITP (io), 16 VDD33 (power), 17 PF6 (io), 18 PF7 (io), 19 PF8/HSADC4 (io), 20 PF9/HSADC5 (io), 21 PF10/HSADC6 (io), 22 VSS (power), 23 XI (io), 24 XO (io), 25 NRST (in), 26 PC0/ADC10/HSADC0 (io), 27 PC1/ADC11/HSADC1 (io), 28 PC2/ADC12/HSADC2/OP3_P0 (io), 29 PC3/ADC13/HSADC3/OP3_N0 (io), 30 VDDIO (power), 31 VSSA (power), 32 VREFP (io), 33 VDD33A (power), 34 PA0/ADC0/OP3_O0 (io), 35 PA1/ADC1 (io), 36 PA2/ADC2/OP3_P1 (io), 37 PA3/ADC3/OP3_N1 (io), 38 VDDIO (power), 39 PA4/ADC4/OP3_O1/DAC1 (io), 40 PA5/ADC5/OP1_O1/DAC2 (io), 41 PA6/ADC6/OP1_P1 (io), 42 PA7/ADC7/OP1_N1 (io), 43 PC4/ADC14/OP1_O0/CMP_N1 (io), 44 PC5/ADC15 (io), 45 PB0/ADC8/OP1_P0/CMP_P0 (io), 46 PB1/ADC9/OP1_N0/OP2_O1/CMP_N0 (io), 47 PB2/CMP_P1 (io), 48 PF11/OP2_P1 (io), 49 PF12/OP2_N1 (io), 50 PF13 (io), 51 VDDIO (power), 52 PE7/OP2_O0 (io), 53 PE8/OP2_N0 (io), 54 PE9/OP2_P0 (io), 55 PE10 (io), 56 PE11 (io), 57 PE12 (io), 58 PE13 (io), 59 PE14 (io), 60 PE15 (io), 61 PB10 (io), 62 PB11 (io), 63 VIO18 (power), 64 VDDIO (power), 65 PB12 (io), 66 PB13 (io), 67 PB14 (io), 68 PB15 (io), 69 PD8 (io), 70 PD9 (io), 71 PD10 (io), 72 PD11 (io), 73 PD12 (io), 74 PD13 (io), 75 PD14 (io), 76 PD15 (io), 77 PF0 (io), 78 PF1 (io), 79 PF2 (io), 80 VDDK (power), 81 VIO18 (power), 82 VDDIO (power), 83 PC6 (io), 84 PC7 (io), 85 PC8 (io), 86 PC9 (io), 87 PA8 (io), 88 PA9/OTG_VBUS (io), 89 PA10/OTG_ID (io), 90 PA11/OTG_DM (io), 91 PA12/OTG_DP (io), 92 PA13 (io), 93 VDD33 (power), 94 PA14 (io), 95 PA15 (io), 96 PC10 (io), 97 PC11 (io), 98 PC12 (io), 99 PD0 (io), 100 PD1 (io), 101 PD2 (io), 102 PD3 (io), 103 PD4 (io), 104 PD5 (io), 105 VIO18 (power), 106 PD6 (io), 107 PD7 (io), 108 PF3 (io), 109 PF4 (io), 110 PF5 (io), 111 PE0 (io), 112 PE1 (io), 113 PF14 (io), 114 VDDIO (power), 115 PB3/CC1 (io), 116 PB4/CC2 (io), 117 PB5 (io), 118 PB6 (io), 119 PB7 (io), 120 PB8/USB2DP/SWCLK (io), 121 PB9/USB2DM/SWDIO (io), 122 VSS (power), 123 SSTXB (io), 124 SSTXA (io), 125 VDD12A (power), 126 SSRXB (io), 127 SSRXA (io), 128 VDD33 (power)

## CH32H417WEU6
designator *
RISC-V FPU HD-MCU, 400MHz, USB3.0, 100M Ethernet, DVP, SDMMC, QSPI, OPA, ADC, DAC
footprint QFN68_8X8 (Footprint not found)
pins: 0 VSS (power), 1 SSTXB (io), 2 SSTXA (io), 3 VDD12A (power), 4 SSRXB (io), 5 SSRXA (io), 6 VDD33 (power), 7 VDDK (power), 8 MDIRN (io), 9 MDIRP (io), 10 MDITN (io), 11 MDITP (io), 12 VDD33 (power), 13 XI (io), 14 XO (io), 15 PC0/ADC10/HSADC0 (io), 16 PC1/ADC11/HSADC1 (io), 17 PC2/ADC12/HSADC2/OP3_P0 (io), 18 PC3/ADC13/HSADC3/OP3_N0 (io), 19 VDD33A (power), 20 PA5/ADC5/OP1_O1/DAC2 (io), 21 PB0/ADC8/OP1_P0/CMP_P0 (io), 22 PB1/ADC9/OP1_N0/CMP_N0 (io), 23 PE13 (io), 24 PE14 (io), 25 PE15 (io), 26 PB10 (io), 27 PB11 (io), 28 VIO18 (power), 29 VDDIO (power), 30 PB12 (io), 31 PB13 (io), 32 PB14 (io), 33 PD10 (io), 34 PD11 (io), 35 PD12 (io), 36 PD13 (io), 37 PD14 (io), 38 PD15 (io), 39 PF0 (io), 40 PF1 (io), 41 PF2 (io), 42 PC6 (io), 43 PC7 (io), 44 PC8 (io), 45 PC9 (io), 46 PA13 (io), 47 PA14 (io), 48 PA15 (io), 49 PC10 (io), 50 PC11 (io), 51 PC12 (io), 52 PD0 (io), 53 PD1 (io), 54 PD2 (io), 55 PD3 (io), 56 PD4 (io), 57 PD5 (io), 58 PD6 (io), 59 PD7 (io), 60 PF3 (io), 61 PF4 (io), 62 PF5 (io), 63 PE0 (io), 64 PE1 (io), 65 PF14 (io), 66 VIO18 (power), 67 PB8/USB2DP/SWCLK (io), 68 PB9/USB2DM/SWDIO (io)

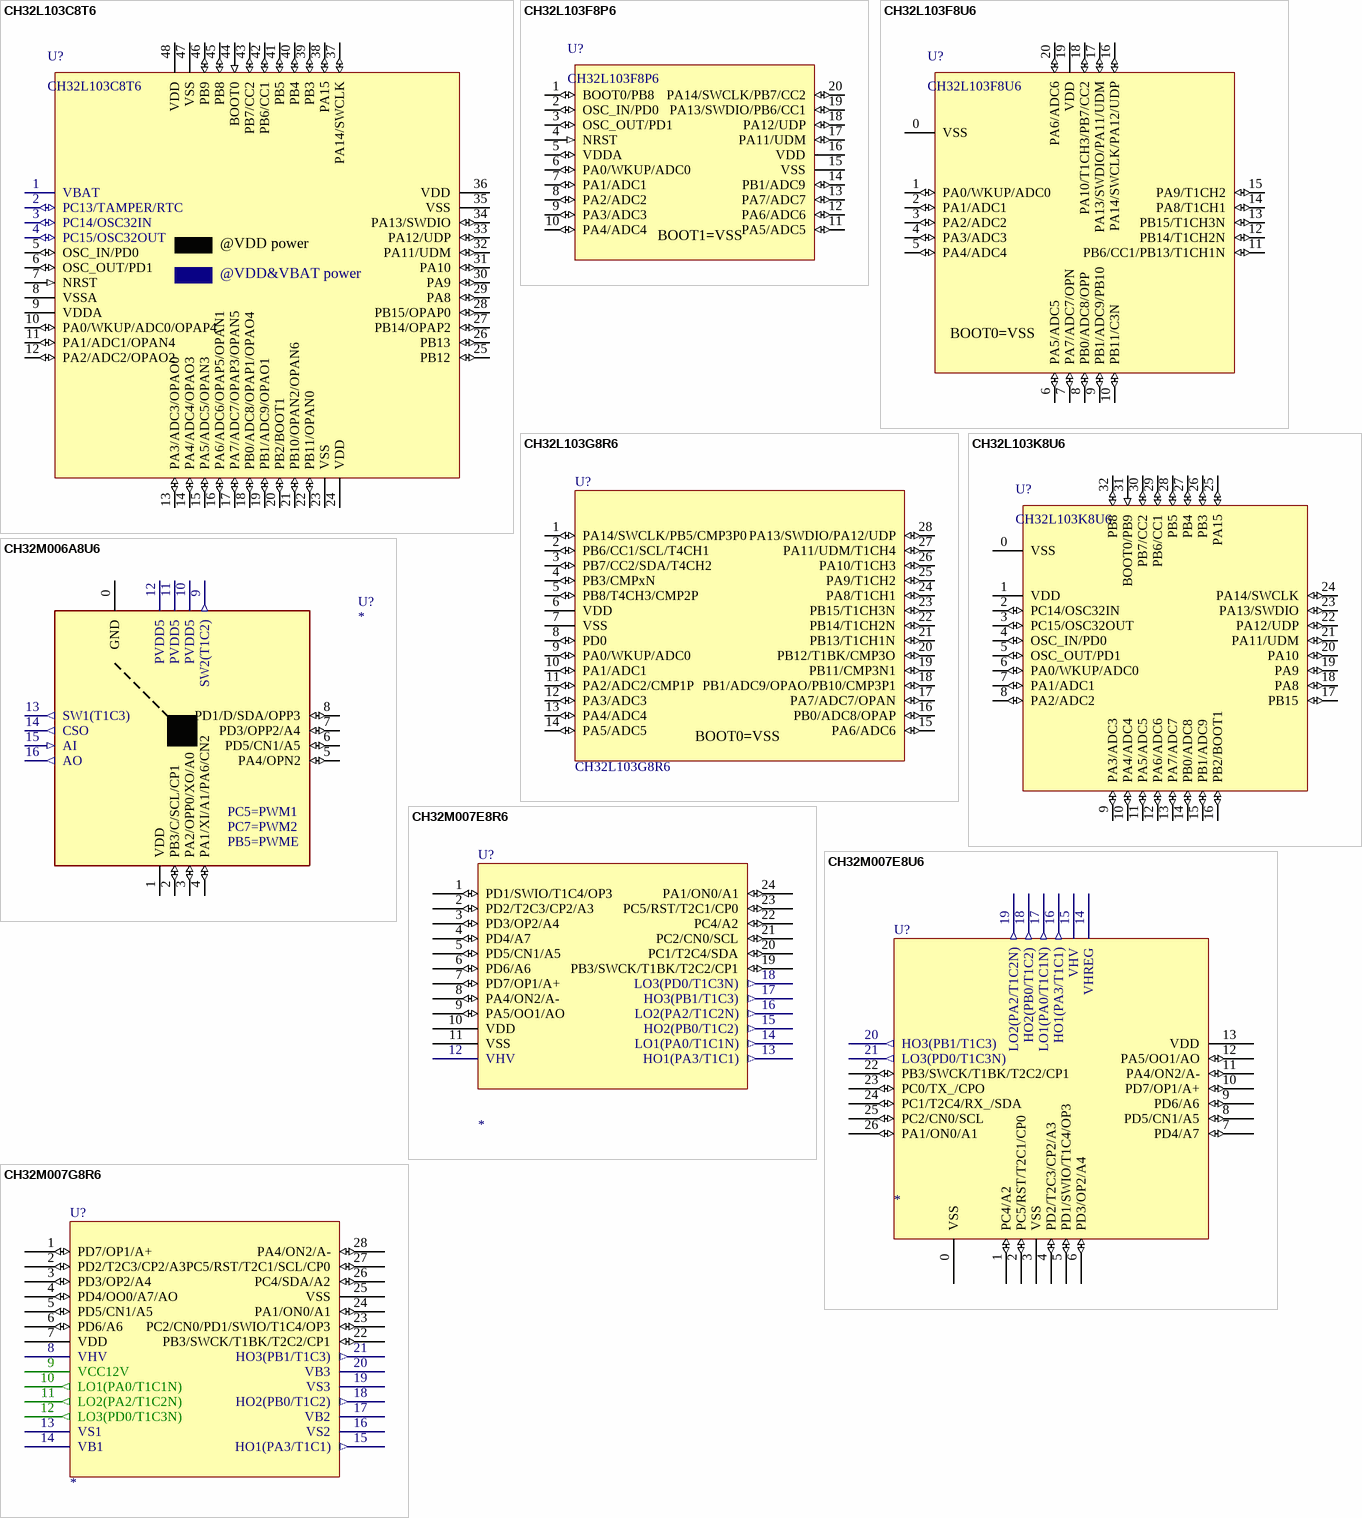
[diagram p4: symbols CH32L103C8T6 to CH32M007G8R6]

## CH32L103C8T6
designator U?
RISC-V LMD-MCU, 96MHz, USB, Type-C/PD, CAN, OPA, lower power
footprint LQFP48
pins: 1 VBAT (power), 2 PC13/TAMPER/RTC (io), 3 PC14/OSC32IN (io), 4 PC15/OSC32OUT (io), 5 OSC_IN/PD0 (io), 6 OSC_OUT/PD1 (io), 7 NRST (in), 8 VSSA (power), 9 VDDA (power), 10 PA0/WKUP/ADC0/OPAP4 (io), 11 PA1/ADC1/OPAN4 (io), 12 PA2/ADC2/OPAO2 (io), 13 PA3/ADC3/OPAO0 (io), 14 PA4/ADC4/OPAO3 (io), 15 PA5/ADC5/OPAN3 (io), 16 PA6/ADC6/OPAP5/OPAN1 (io), 17 PA7/ADC7/OPAP3/OPAN5 (io), 18 PB0/ADC8/OPAP1/OPAO4 (io), 19 PB1/ADC9/OPAO1 (io), 20 PB2/BOOT1 (io), 21 PB10/OPAN2/OPAN6 (io), 22 PB11/OPAN0 (io), 23 VSS (power), 24 VDD (power), 25 PB12 (io), 26 PB13 (io), 27 PB14/OPAP2 (io), 28 PB15/OPAP0 (io), 29 PA8 (io), 30 PA9 (io), 31 PA10 (io), 32 PA11/UDM (io), 33 PA12/UDP (io), 34 PA13/SWDIO (io), 35 VSS (power), 36 VDD (power), 37 PA14/SWCLK (io), 38 PA15 (io), 39 PB3 (io), 40 PB4 (io), 41 PB5 (io), 42 PB6/CC1 (io), 43 PB7/CC2 (io), 44 BOOT0 (in), 45 PB8 (io), 46 PB9 (io), 47 VSS (power), 48 VDD (power)

## CH32L103F8P6
designator U?
RISC-V LMD-MCU, 96MHz, USB, Type-C/PD, CAN, OPA, lower power
footprint TSSOP20 (Footprint not found)
pins: 1 BOOT0/PB8 (io), 2 OSC_IN/PD0 (io), 3 OSC_OUT/PD1 (io), 4 NRST (in), 5 VDDA (io), 6 PA0/WKUP/ADC0 (io), 7 PA1/ADC1 (io), 8 PA2/ADC2 (io), 9 PA3/ADC3 (io), 10 PA4/ADC4 (io), 11 PA5/ADC5 (io), 12 PA6/ADC6 (io), 13 PA7/ADC7 (io), 14 PB1/ADC9 (io), 15 VSS (power), 16 VDD (power), 17 PA11/UDM (io), 18 PA12/UDP (io), 19 PA13/SWDIO/PB6/CC1 (io), 20 PA14/SWCLK/PB7/CC2 (io)

## CH32L103F8U6
designator U?
RISC-V LMD-MCU, 96MHz, USB, Type-C/PD-5K1, CAN, OPA, lower power
footprint QFN20_3X3
pins: 0 VSS (power), 1 PA0/WKUP/ADC0 (io), 2 PA1/ADC1 (io), 3 PA2/ADC2 (io), 4 PA3/ADC3 (io), 5 PA4/ADC4 (io), 6 PA5/ADC5 (io), 7 PA7/ADC7/OPN (io), 8 PB0/ADC8/OPP (io), 9 PB1/ADC9/PB10 (io), 10 PB11/C3N (io), 11 PB6/CC1/PB13/T1CH1N (io), 12 PB14/T1CH2N (io), 13 PB15/T1CH3N (io), 14 PA8/T1CH1 (io), 15 PA9/T1CH2 (io), 16 PA14/SWCLK/PA12/UDP (io), 17 PA13/SWDIO/PA11/UDM (io), 18 PA10/T1CH3/PB7/CC2 (io), 19 VDD (power), 20 PA6/ADC6 (io)

## CH32L103G8R6
designator U?
RISC-V LMD-MCU, 96MHz, USB, Type-C, CAN, OPA, lower power
footprint QSOP28
pins: 1 PA14/SWCLK/PB5/CMP3P0 (io), 2 PB6/CC1/SCL/T4CH1 (io), 3 PB7/CC2/SDA/T4CH2 (io), 4 PB3/CMPxN (io), 5 PB8/T4CH3/CMP2P (io), 6 VDD (power), 7 VSS (power), 8 PD0 (io), 9 PA0/WKUP/ADC0 (io), 10 PA1/ADC1 (io), 11 PA2/ADC2/CMP1P (io), 12 PA3/ADC3 (io), 13 PA4/ADC4 (io), 14 PA5/ADC5 (io), 15 PA6/ADC6 (io), 16 PB0/ADC8/OPAP (io), 17 PA7/ADC7/OPAN (io), 18 PB1/ADC9/OPAO/PB10/CMP3P1 (io), 19 PB11/CMP3N1 (io), 20 PB12/T1BK/CMP3O (io), 21 PB13/T1CH1N (io), 22 PB14/T1CH2N (io), 23 PB15/T1CH3N (io), 24 PA8/T1CH1 (io), 25 PA9/T1CH2 (io), 26 PA10/T1CH3 (io), 27 PA11/UDM/T1CH4 (io), 28 PA13/SWDIO/PA12/UDP (io)

## CH32L103K8U6
designator U?
RISC-V LMD-MCU, 96MHz, USB, Type-C/PD-5K1, CAN, OPA, lower power
footprint QFN32_4X4
pins: 0 VSS (power), 1 VDD (power), 2 PC14/OSC32IN (io), 3 PC15/OSC32OUT (io), 4 OSC_IN/PD0 (io), 5 OSC_OUT/PD1 (io), 6 PA0/WKUP/ADC0 (io), 7 PA1/ADC1 (io), 8 PA2/ADC2 (io), 9 PA3/ADC3 (io), 10 PA4/ADC4 (io), 11 PA5/ADC5 (io), 12 PA6/ADC6 (io), 13 PA7/ADC7 (io), 14 PB0/ADC8 (io), 15 PB1/ADC9 (io), 16 PB2/BOOT1 (io), 17 PB15 (io), 18 PA8 (io), 19 PA9 (io), 20 PA10 (io), 21 PA11/UDM (io), 22 PA12/UDP (io), 23 PA13/SWDIO (io), 24 PA14/SWCLK (io), 25 PA15 (io), 26 PB3 (io), 27 PB4 (io), 28 PB5 (io), 29 PB6/CC1 (io), 30 PB7/CC2 (io), 31 BOOT0/PB9 (in), 32 PB8 (io)

## CH32M006A8U6
designator U?
RISC-V MCU, 48MHz, OPA/CMP/UART/I2C, 5V Full-Bridge Power Stage
footprint QFN16_3X3 (Footprint not found)
pins: 0 GND (power), 1 VDD (power), 2 PB3/C/SCL/CP1 (io), 3 PA2/OPP0/XO/A0 (io), 4 PA1/XI/A1/PA6/CN2 (io), 5 PA4/OPN2 (io), 6 PD5/CN1/A5 (io), 7 PD3/OPP2/A4 (io), 8 PD1/D/SDA/OPP3 (io), 9 SW2(T1C2) (out), 10 PVDD5 (power), 11 PVDD5 (power), 12 PVDD5 (power), 13 SW1(T1C3) (out), 14 CSO (out), 15 AI (in), 16 AO (out)

## CH32M007E8R6
designator U?
RISC-V MCU, 48MHz, OPA/CMP/UART/I2C, 24V P/NMOS gate driver for motor
footprint QSOP24 (Footprint not found)
pins: 1 PD1/SWIO/T1C4/OP3 (io), 2 PD2/T2C3/CP2/A3 (io), 3 PD3/OP2/A4 (io), 4 PD4/A7 (io), 5 PD5/CN1/A5 (io), 6 PD6/A6 (io), 7 PD7/OP1/A+ (io), 8 PA4/ON2/A- (io), 9 PA5/OO1/AO (io), 10 VDD (power), 11 VSS (power), 12 VHV (power), 13 HO1(PA3/T1C1) (out), 14 LO1(PA0/T1C1N) (out), 15 HO2(PB0/T1C2) (out), 16 LO2(PA2/T1C2N) (out), 17 HO3(PB1/T1C3) (out), 18 LO3(PD0/T1C3N) (out), 19 PB3/SWCK/T1BK/T2C2/CP1 (io), 20 PC1/T2C4/SDA (io), 21 PC2/CN0/SCL (io), 22 PC4/A2 (io), 23 PC5/RST/T2C1/CP0 (io), 24 PA1/ON0/A1 (io)

## CH32M007E8U6
designator U?
RISC-V MCU, 48MHz, OPA/CMP/UART/I2C, 24V P/NMOS gate driver for motor
footprint QFN26C_3X3 (Footprint not found)
pins: 0 VSS (power), 1 PC4/A2 (io), 2 PC5/RST/T2C1/CP0 (io), 3 VSS (power), 4 PD2/T2C3/CP2/A3 (io), 5 PD1/SWIO/T1C4/OP3 (io), 6 PD3/OP2/A4 (io), 7 PD4/A7 (io), 8 PD5/CN1/A5 (io), 9 PD6/A6 (io), 10 PD7/OP1/A+ (io), 11 PA4/ON2/A- (io), 12 PA5/OO1/AO (io), 13 VDD (power), 14 VHREG (power), 15 VHV (power), 16 HO1(PA3/T1C1) (out), 17 LO1(PA0/T1C1N) (out), 18 HO2(PB0/T1C2) (out), 19 LO2(PA2/T1C2N) (out), 20 HO3(PB1/T1C3) (out), 21 LO3(PD0/T1C3N) (out), 22 PB3/SWCK/T1BK/T2C2/CP1 (io), 23 PC0/TX_/CPO (io), 24 PC1/T2C4/RX_/SDA (io), 25 PC2/CN0/SCL (io), 26 PA1/ON0/A1 (io)

## CH32M007G8R6
designator U?
RISC-V MCU, 48MHz, OPA/CMP/UART/I2C, 48V NMOS gate driver for motor
footprint QSOP28
pins: 1 PD7/OP1/A+ (io), 2 PD2/T2C3/CP2/A3 (io), 3 PD3/OP2/A4 (io), 4 PD4/OO0/A7/AO (io), 5 PD5/CN1/A5 (io), 6 PD6/A6 (io), 7 VDD (power), 8 VHV (power), 9 VCC12V (power), 10 LO1(PA0/T1C1N) (out), 11 LO2(PA2/T1C2N) (out), 12 LO3(PD0/T1C3N) (out), 13 VS1 (power), 14 VB1 (power), 15 HO1(PA3/T1C1) (out), 16 VS2 (power), 17 VB2 (power), 18 HO2(PB0/T1C2) (out), 19 VS3 (power), 20 VB3 (power), 21 HO3(PB1/T1C3) (out), 22 PB3/SWCK/T1BK/T2C2/CP1 (io), 23 PC2/CN0/PD1/SWIO/T1C4/OP3 (io), 24 PA1/ON0/A1 (io), 25 VSS (power), 26 PC4/SDA/A2 (io), 27 PC5/RST/T2C1/SCL/CP0 (io), 28 PA4/ON2/A- (io)
2 alternate drawings of the same symbol

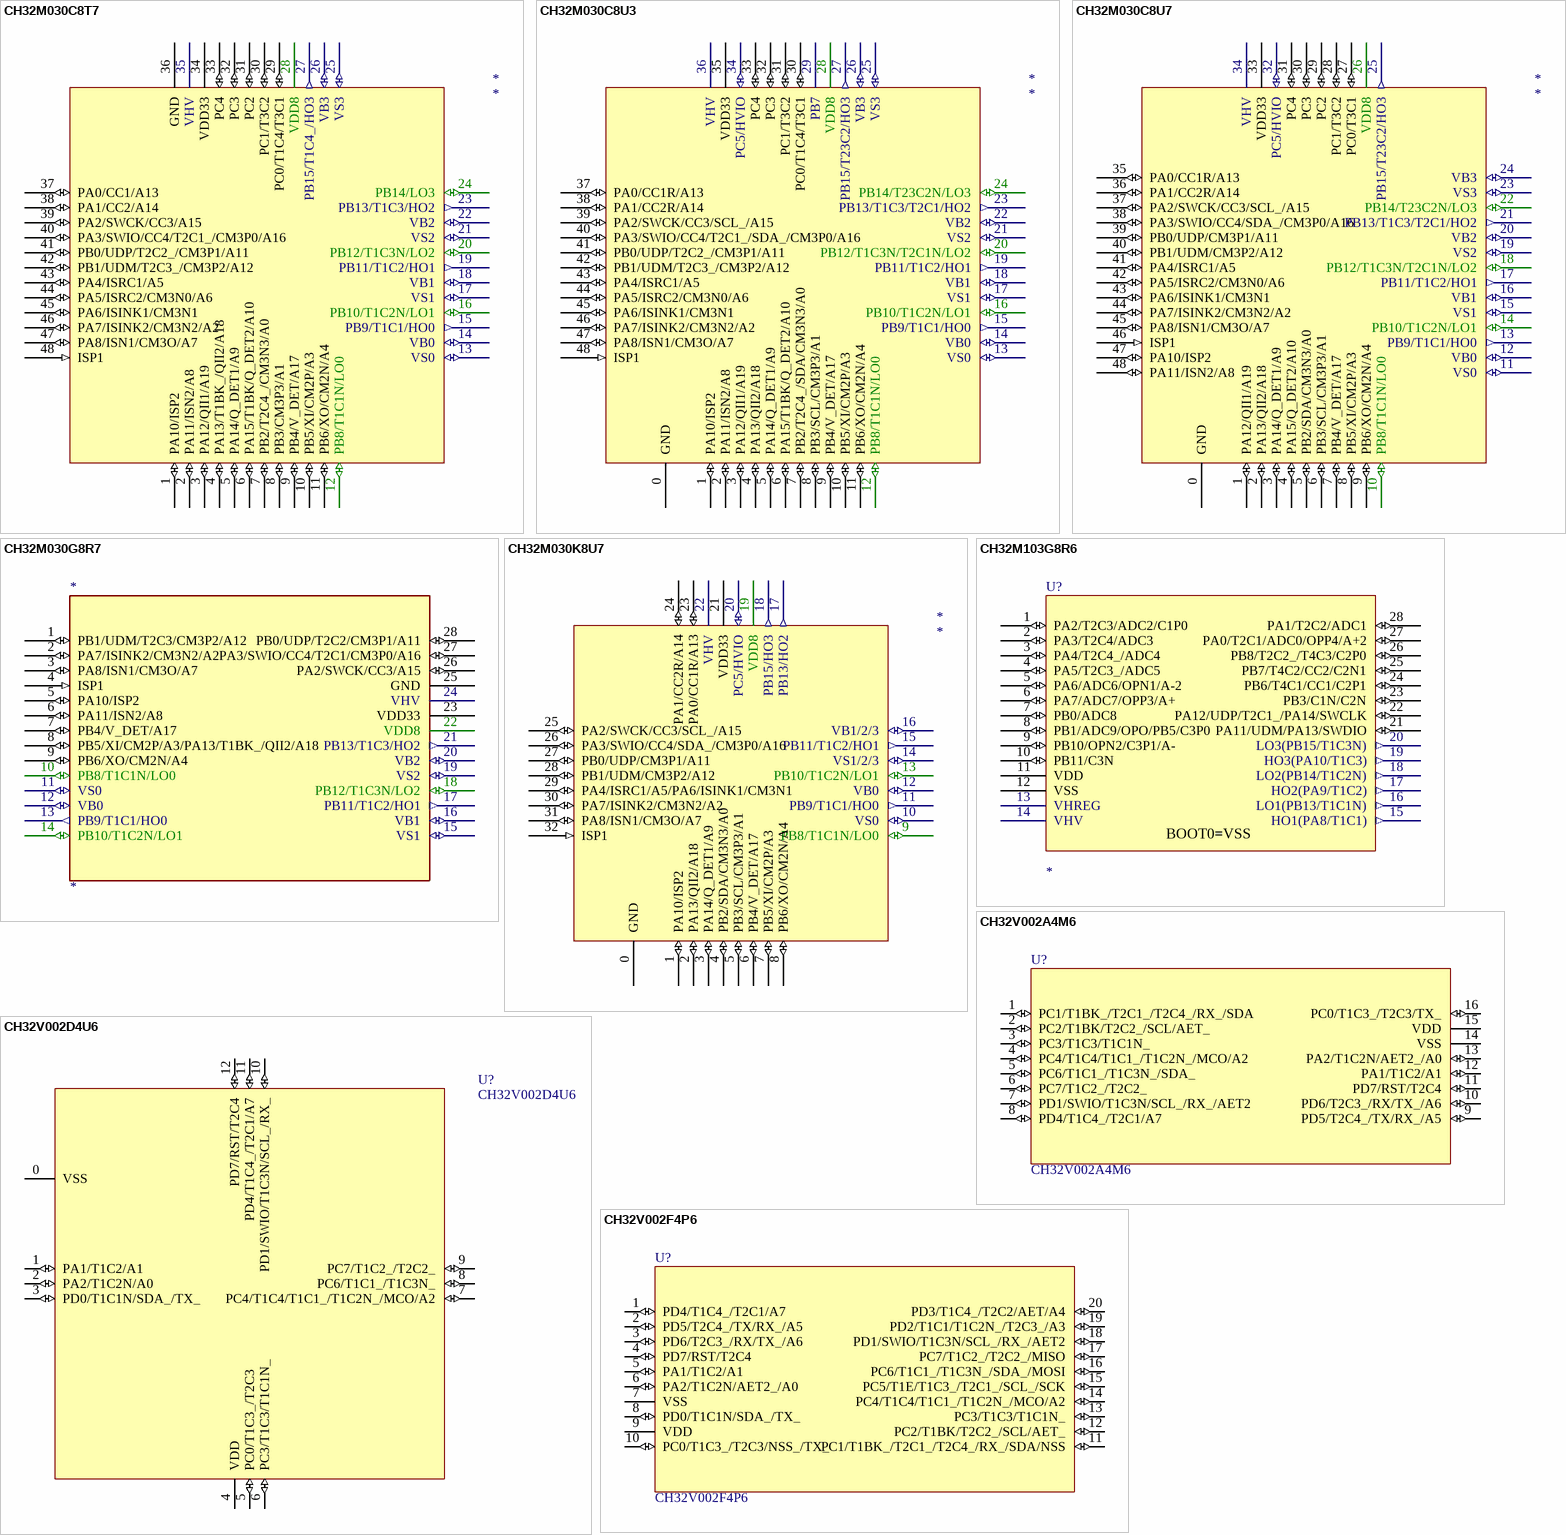
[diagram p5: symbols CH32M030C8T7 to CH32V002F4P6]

## CH32M030C8T7
designator *
RISC-V MCU, 72MHz, USB, Type-C/PD, OPA, CMP, 28V gate driver
footprint LQFP48
pins: 1 PA10/ISP2 (io), 2 PA11/ISN2/A8 (io), 3 PA12/QII1/A19 (io), 4 PA13/T1BK_/QII2/A18 (io), 5 PA14/Q_DET1/A9 (io), 6 PA15/T1BK/Q_DET2/A10 (io), 7 PB2/T2C4_/CM3N3/A0 (io), 8 PB3/CM3P3/A1 (io), 9 PB4/V_DET/A17 (io), 10 PB5/XI/CM2P/A3 (io), 11 PB6/XO/CM2N/A4 (io), 12 PB8/T1C1N/LO0 (io), 13 VS0 (io), 14 VB0 (io), 15 PB9/T1C1/HO0 (out), 16 PB10/T1C2N/LO1 (io), 17 VS1 (io), 18 VB1 (io), 19 PB11/T1C2/HO1 (out), 20 PB12/T1C3N/LO2 (io), 21 VS2 (io), 22 VB2 (io), 23 PB13/T1C3/HO2 (out), 24 PB14/LO3 (io), 25 VS3 (io), 26 VB3 (io), 27 PB15/T1C4_/HO3 (out), 28 VDD8 (power), 29 PC0/T1C4/T3C1 (io), 30 PC1/T3C2 (io), 31 PC2 (io), 32 PC3 (io), 33 PC4 (io), 34 VDD33 (power), 35 VHV (power), 36 GND (power), 37 PA0/CC1/A13 (io), 38 PA1/CC2/A14 (io), 39 PA2/SWCK/CC3/A15 (io), 40 PA3/SWIO/CC4/T2C1_/CM3P0/A16 (io), 41 PB0/UDP/T2C2_/CM3P1/A11 (io), 42 PB1/UDM/T2C3_/CM3P2/A12 (io), 43 PA4/ISRC1/A5 (io), 44 PA5/ISRC2/CM3N0/A6 (io), 45 PA6/ISINK1/CM3N1 (io), 46 PA7/ISINK2/CM3N2/A2 (io), 47 PA8/ISN1/CM3O/A7 (io), 48 ISP1 (in)

## CH32M030C8U3
designator *
RISC-V MCU, 72MHz, USB, Type-C/PD, OPA, CMP, 28V gate driver
footprint QFN48_7X7 (Footprint not found)
pins: 0 GND (power), 1 PA10/ISP2 (io), 2 PA11/ISN2/A8 (io), 3 PA12/QII1/A19 (io), 4 PA13/QII2/A18 (io), 5 PA14/Q_DET1/A9 (io), 6 PA15/T1BK/Q_DET2/A10 (io), 7 PB2/T2C4_/SDA/CM3N3/A0 (io), 8 PB3/SCL/CM3P3/A1 (io), 9 PB4/V_DET/A17 (io), 10 PB5/XI/CM2P/A3 (io), 11 PB6/XO/CM2N/A4 (io), 12 PB8/T1C1N/LO0 (io), 13 VS0 (io), 14 VB0 (io), 15 PB9/T1C1/HO0 (out), 16 PB10/T1C2N/LO1 (io), 17 VS1 (io), 18 VB1 (io), 19 PB11/T1C2/HO1 (out), 20 PB12/T1C3N/T2C1N/LO2 (io), 21 VS2 (io), 22 VB2 (io), 23 PB13/T1C3/T2C1/HO2 (out), 24 PB14/T23C2N/LO3 (io), 25 VS3 (io), 26 VB3 (io), 27 PB15/T23C2/HO3 (out), 28 VDD8 (power), 29 PB7 (oc), 30 PC0/T1C4/T3C1 (io), 31 PC1/T3C2 (io), 32 PC3 (io), 33 PC4 (io), 34 PC5/HVIO (io), 35 VDD33 (power), 36 VHV (power), 37 PA0/CC1R/A13 (io), 38 PA1/CC2R/A14 (io), 39 PA2/SWCK/CC3/SCL_/A15 (io), 40 PA3/SWIO/CC4/T2C1_/SDA_/CM3P0/A16 (io), 41 PB0/UDP/T2C2_/CM3P1/A11 (io), 42 PB1/UDM/T2C3_/CM3P2/A12 (io), 43 PA4/ISRC1/A5 (io), 44 PA5/ISRC2/CM3N0/A6 (io), 45 PA6/ISINK1/CM3N1 (io), 46 PA7/ISINK2/CM3N2/A2 (io), 47 PA8/ISN1/CM3O/A7 (io), 48 ISP1 (in)

## CH32M030C8U7
designator *
RISC-V MCU, 72MHz, USB, Type-C/PD, OPA, CMP, 28V gate driver
footprint QFN48_5X5
pins: 0 GND (power), 1 PA12/QII1/A19 (io), 2 PA13/QII2/A18 (io), 3 PA14/Q_DET1/A9 (io), 4 PA15/Q_DET2/A10 (io), 5 PB2/SDA/CM3N3/A0 (io), 6 PB3/SCL/CM3P3/A1 (io), 7 PB4/V_DET/A17 (io), 8 PB5/XI/CM2P/A3 (io), 9 PB6/XO/CM2N/A4 (io), 10 PB8/T1C1N/LO0 (io), 11 VS0 (io), 12 VB0 (io), 13 PB9/T1C1/HO0 (out), 14 PB10/T1C2N/LO1 (io), 15 VS1 (io), 16 VB1 (io), 17 PB11/T1C2/HO1 (out), 18 PB12/T1C3N/T2C1N/LO2 (io), 19 VS2 (io), 20 VB2 (io), 21 PB13/T1C3/T2C1/HO2 (out), 22 PB14/T23C2N/LO3 (io), 23 VS3 (io), 24 VB3 (io), 25 PB15/T23C2/HO3 (out), 26 VDD8 (power), 27 PC0/T3C1 (io), 28 PC1/T3C2 (io), 29 PC2 (io), 30 PC3 (io), 31 PC4 (io), 32 PC5/HVIO (io), 33 VDD33 (power), 34 VHV (power), 35 PA0/CC1R/A13 (io), 36 PA1/CC2R/A14 (io), 37 PA2/SWCK/CC3/SCL_/A15 (io), 38 PA3/SWIO/CC4/SDA_/CM3P0/A16 (io), 39 PB0/UDP/CM3P1/A11 (io), 40 PB1/UDM/CM3P2/A12 (io), 41 PA4/ISRC1/A5 (io), 42 PA5/ISRC2/CM3N0/A6 (io), 43 PA6/ISINK1/CM3N1 (io), 44 PA7/ISINK2/CM3N2/A2 (io), 45 PA8/ISN1/CM3O/A7 (io), 46 ISP1 (in), 47 PA10/ISP2 (io), 48 PA11/ISN2/A8 (io)

## CH32M030G8R7
designator *
RISC-V MCU, 72MHz, USB, Type-C/PD, OPA, CMP, 28V gate driver
footprint QSOP28
pins: 1 PB1/UDM/T2C3/CM3P2/A12 (io), 2 PA7/ISINK2/CM3N2/A2 (io), 3 PA8/ISN1/CM3O/A7 (io), 4 ISP1 (in), 5 PA10/ISP2 (io), 6 PA11/ISN2/A8 (io), 7 PB4/V_DET/A17 (io), 8 PB5/XI/CM2P/A3/PA13/T1BK_/QII2/A18 (io), 9 PB6/XO/CM2N/A4 (io), 10 PB8/T1C1N/LO0 (io), 11 VS0 (io), 12 VB0 (io), 13 PB9/T1C1/HO0 (out), 14 PB10/T1C2N/LO1 (io), 15 VS1 (io), 16 VB1 (io), 17 PB11/T1C2/HO1 (out), 18 PB12/T1C3N/LO2 (io), 19 VS2 (io), 20 VB2 (io), 21 PB13/T1C3/HO2 (out), 22 VDD8 (power), 23 VDD33 (power), 24 VHV (power), 25 GND (power), 26 PA2/SWCK/CC3/A15 (io), 27 PA3/SWIO/CC4/T2C1/CM3P0/A16 (io), 28 PB0/UDP/T2C2/CM3P1/A11 (io)

## CH32M030K8U7
designator *
RISC-V MCU, 72MHz, USB, Type-C/PD, OPA, CMP, 28V gate driver
footprint QFN32_4X4
pins: 0 GND (power), 1 PA10/ISP2 (io), 2 PA13/QII2/A18 (io), 3 PA14/Q_DET1/A9 (io), 4 PB2/SDA/CM3N3/A0 (io), 5 PB3/SCL/CM3P3/A1 (io), 6 PB4/V_DET/A17 (io), 7 PB5/XI/CM2P/A3 (io), 8 PB6/XO/CM2N/A4 (io), 9 PB8/T1C1N/LO0 (io), 10 VS0 (io), 11 PB9/T1C1/HO0 (out), 12 VB0 (io), 13 PB10/T1C2N/LO1 (io), 14 VS1/2/3 (io), 15 PB11/T1C2/HO1 (out), 16 VB1/2/3 (io), 17 PB13/HO2 (out), 18 PB15/HO3 (out), 19 VDD8 (power), 20 PC5/HVIO (io), 21 VDD33 (power), 22 VHV (power), 23 PA0/CC1R/A13 (io), 24 PA1/CC2R/A14 (io), 25 PA2/SWCK/CC3/SCL_/A15 (io), 26 PA3/SWIO/CC4/SDA_/CM3P0/A16 (io), 27 PB0/UDP/CM3P1/A11 (io), 28 PB1/UDM/CM3P2/A12 (io), 29 PA4/ISRC1/A5/PA6/ISINK1/CM3N1 (io), 30 PA7/ISINK2/CM3N2/A2 (io), 31 PA8/ISN1/CM3O/A7 (io), 32 ISP1 (in)

## CH32M103G8R6
designator U?
RISC-V MCU, 96MHz, OPA/CMP/USB/CAN, 24V P/NMOS gate driver for motor
footprint QSOP28 (Footprint not found)
pins: 1 PA2/T2C3/ADC2/C1P0 (io), 2 PA3/T2C4/ADC3 (io), 3 PA4/T2C4_/ADC4 (io), 4 PA5/T2C3_/ADC5 (io), 5 PA6/ADC6/OPN1/A-2 (io), 6 PA7/ADC7/OPP3/A+ (io), 7 PB0/ADC8 (io), 8 PB1/ADC9/OPO/PB5/C3P0 (io), 9 PB10/OPN2/C3P1/A- (io), 10 PB11/C3N (io), 11 VDD (power), 12 VSS (power), 13 VHREG (power), 14 VHV (power), 15 HO1(PA8/T1C1) (out), 16 LO1(PB13/T1C1N) (out), 17 HO2(PA9/T1C2) (out), 18 LO2(PB14/T1C2N) (out), 19 HO3(PA10/T1C3) (out), 20 LO3(PB15/T1C3N) (out), 21 PA11/UDM/PA13/SWDIO (io), 22 PA12/UDP/T2C1_/PA14/SWCLK (io), 23 PB3/C1N/C2N (io), 24 PB6/T4C1/CC1/C2P1 (io), 25 PB7/T4C2/CC2/C2N1 (io), 26 PB8/T2C2_/T4C3/C2P0 (io), 27 PA0/T2C1/ADC0/OPP4/A+2 (io), 28 PA1/T2C2/ADC1 (io)

## CH32V002A4M6
designator U?
RISC-V MCU, 48MHz, ADC/UART/I2C
footprint SOP16
pins: 1 PC1/T1BK_/T2C1_/T2C4_/RX_/SDA (io), 2 PC2/T1BK/T2C2_/SCL/AET_ (io), 3 PC3/T1C3/T1C1N_ (io), 4 PC4/T1C4/T1C1_/T1C2N_/MCO/A2 (io), 5 PC6/T1C1_/T1C3N_/SDA_ (io), 6 PC7/T1C2_/T2C2_ (io), 7 PD1/SWIO/T1C3N/SCL_/RX_/AET2 (io), 8 PD4/T1C4_/T2C1/A7 (io), 9 PD5/T2C4_/TX/RX_/A5 (io), 10 PD6/T2C3_/RX/TX_/A6 (io), 11 PD7/RST/T2C4 (io), 12 PA1/T1C2/A1 (io), 13 PA2/T1C2N/AET2_/A0 (io), 14 VSS (power), 15 VDD (power), 16 PC0/T1C3_/T2C3/TX_ (io)

## CH32V002D4U6
designator U?
RISC-V MCU, 48MHz, ADC/UART/I2C
footprint QFN12_2X2
pins: 0 VSS (power), 1 PA1/T1C2/A1 (io), 2 PA2/T1C2N/A0 (io), 3 PD0/T1C1N/SDA_/TX_ (io), 4 VDD (power), 5 PC0/T1C3_/T2C3 (io), 6 PC3/T1C3/T1C1N_ (io), 7 PC4/T1C4/T1C1_/T1C2N_/MCO/A2 (io), 8 PC6/T1C1_/T1C3N_ (io), 9 PC7/T1C2_/T2C2_ (io), 10 PD1/SWIO/T1C3N/SCL_/RX_ (io), 11 PD4/T1C4_/T2C1/A7 (io), 12 PD7/RST/T2C4 (io)

## CH32V002F4P6
designator U?
RISC-V MCU, 48MHz, ADC/UART/I2C/SPI
footprint TSSOP20
pins: 1 PD4/T1C4_/T2C1/A7 (io), 2 PD5/T2C4_/TX/RX_/A5 (io), 3 PD6/T2C3_/RX/TX_/A6 (io), 4 PD7/RST/T2C4 (io), 5 PA1/T1C2/A1 (io), 6 PA2/T1C2N/AET2_/A0 (io), 7 VSS (power), 8 PD0/T1C1N/SDA_/TX_ (io), 9 VDD (power), 10 PC0/T1C3_/T2C3/NSS_/TX_ (io), 11 PC1/T1BK_/T2C1_/T2C4_/RX_/SDA/NSS (io), 12 PC2/T1BK/T2C2_/SCL/AET_ (io), 13 PC3/T1C3/T1C1N_ (io), 14 PC4/T1C4/T1C1_/T1C2N_/MCO/A2 (io), 15 PC5/T1E/T1C3_/T2C1_/SCL_/SCK (io), 16 PC6/T1C1_/T1C3N_/SDA_/MOSI (io), 17 PC7/T1C2_/T2C2_/MISO (io), 18 PD1/SWIO/T1C3N/SCL_/RX_/AET2 (io), 19 PD2/T1C1/T1C2N_/T2C3_/A3 (io), 20 PD3/T1C4_/T2C2/AET/A4 (io)

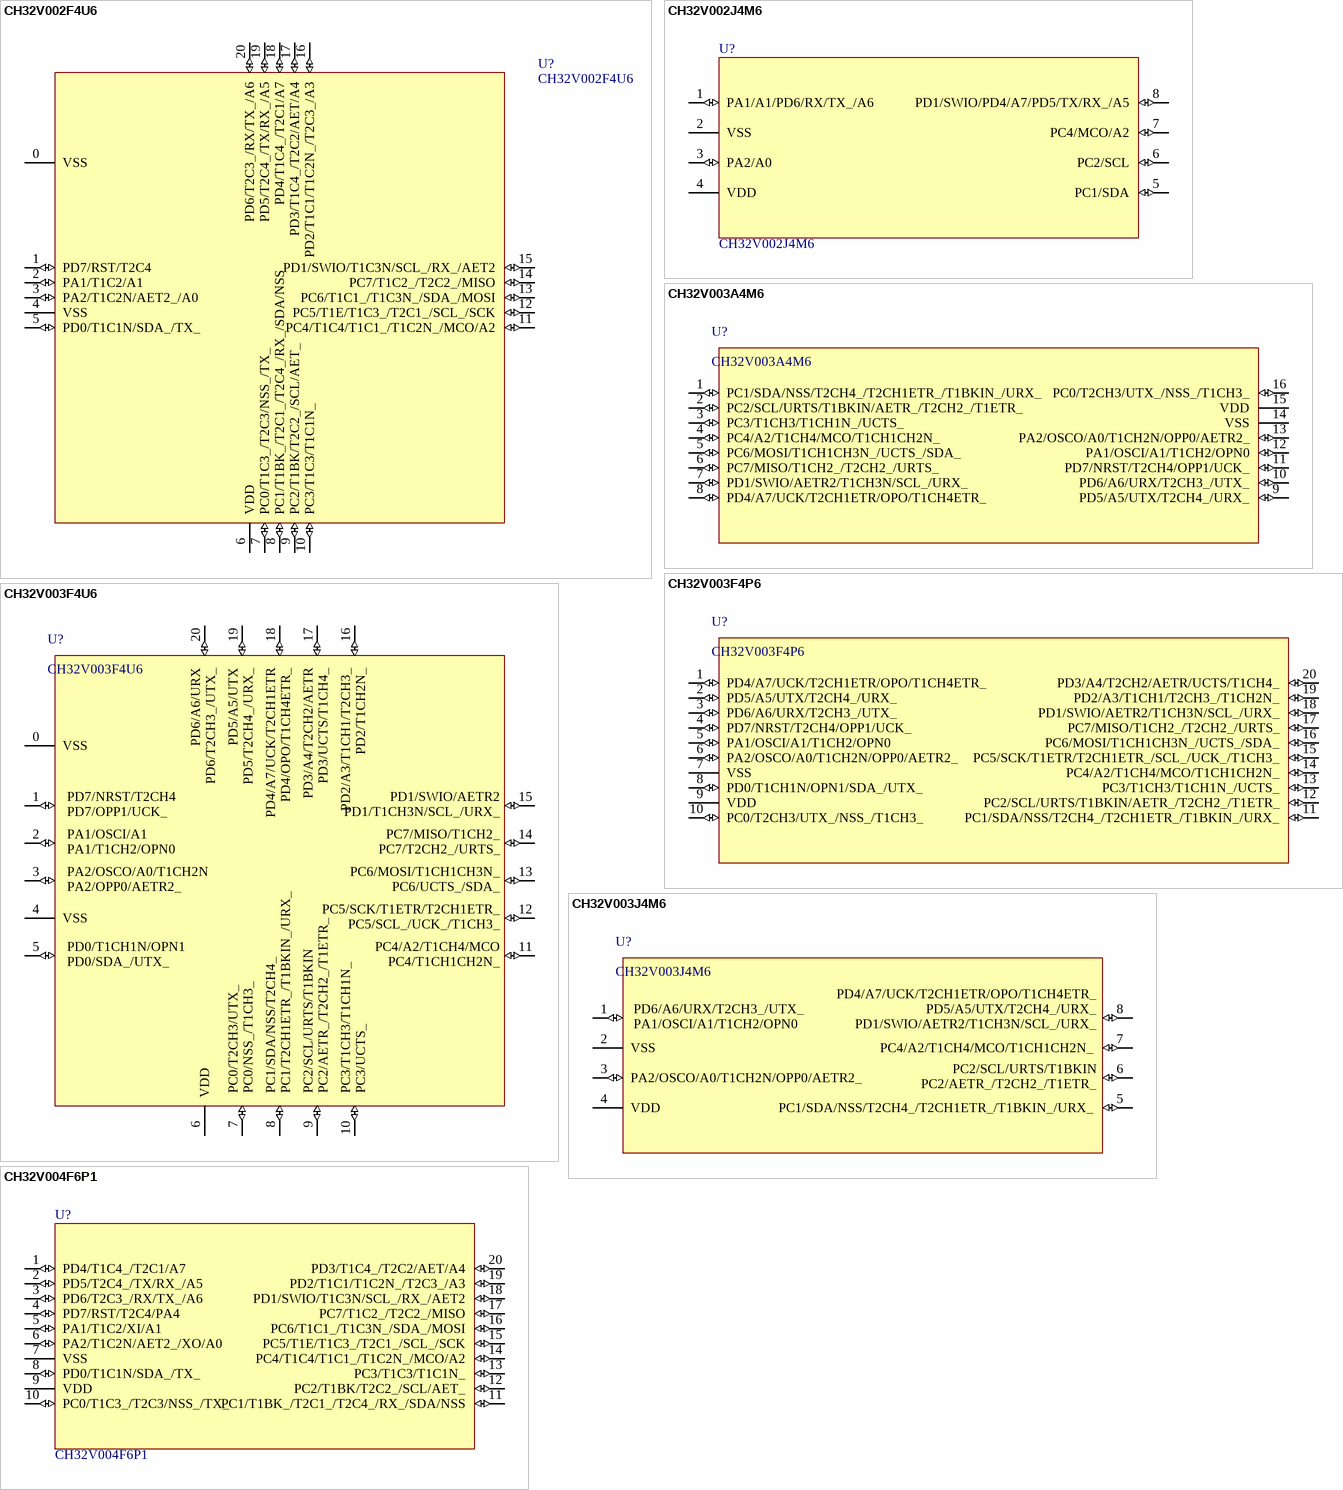
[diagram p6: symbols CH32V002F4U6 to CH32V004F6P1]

## CH32V002F4U6
designator U?
RISC-V MCU, 48MHz, ADC/UART/I2C/SPI
footprint QFN20_3X3
pins: 0 VSS (power), 1 PD7/RST/T2C4 (io), 2 PA1/T1C2/A1 (io), 3 PA2/T1C2N/AET2_/A0 (io), 4 VSS (power), 5 PD0/T1C1N/SDA_/TX_ (io), 6 VDD (power), 7 PC0/T1C3_/T2C3/NSS_/TX_ (io), 8 PC1/T1BK_/T2C1_/T2C4_/RX_/SDA/NSS (io), 9 PC2/T1BK/T2C2_/SCL/AET_ (io), 10 PC3/T1C3/T1C1N_ (io), 11 PC4/T1C4/T1C1_/T1C2N_/MCO/A2 (io), 12 PC5/T1E/T1C3_/T2C1_/SCL_/SCK (io), 13 PC6/T1C1_/T1C3N_/SDA_/MOSI (io), 14 PC7/T1C2_/T2C2_/MISO (io), 15 PD1/SWIO/T1C3N/SCL_/RX_/AET2 (io), 16 PD2/T1C1/T1C2N_/T2C3_/A3 (io), 17 PD3/T1C4_/T2C2/AET/A4 (io), 18 PD4/T1C4_/T2C1/A7 (io), 19 PD5/T2C4_/TX/RX_/A5 (io), 20 PD6/T2C3_/RX/TX_/A6 (io)

## CH32V002J4M6
designator U?
RISC-V MCU, 48MHz, ADC/UART/I2C
footprint SOP8
pins: 1 PA1/A1/PD6/RX/TX_/A6 (io), 2 VSS (power), 3 PA2/A0 (io), 4 VDD (power), 5 PC1/SDA (io), 6 PC2/SCL (io), 7 PC4/MCO/A2 (io), 8 PD1/SWIO/PD4/A7/PD5/TX/RX_/A5 (io)

## CH32V003A4M6
designator U?
RISC-V MCU, 48MHz
footprint SOP16
pins: 1 PC1/SDA/NSS/T2CH4_/T2CH1ETR_/T1BKIN_/URX_ (io), 2 PC2/SCL/URTS/T1BKIN/AETR_/T2CH2_/T1ETR_ (io), 3 PC3/T1CH3/T1CH1N_/UCTS_ (io), 4 PC4/A2/T1CH4/MCO/T1CH1CH2N_ (io), 5 PC6/MOSI/T1CH1CH3N_/UCTS_/SDA_ (io), 6 PC7/MISO/T1CH2_/T2CH2_/URTS_ (io), 7 PD1/SWIO/AETR2/T1CH3N/SCL_/URX_ (io), 8 PD4/A7/UCK/T2CH1ETR/OPO/T1CH4ETR_ (io), 9 PD5/A5/UTX/T2CH4_/URX_ (io), 10 PD6/A6/URX/T2CH3_/UTX_ (io), 11 PD7/NRST/T2CH4/OPP1/UCK_ (io), 12 PA1/OSCI/A1/T1CH2/OPN0 (io), 13 PA2/OSCO/A0/T1CH2N/OPP0/AETR2_ (io), 14 VSS (power), 15 VDD (power), 16 PC0/T2CH3/UTX_/NSS_/T1CH3_ (io)

## CH32V003F4P6
designator U?
RISC-V MCU, 48MHz
footprint TSSOP20
pins: 1 PD4/A7/UCK/T2CH1ETR/OPO/T1CH4ETR_ (io), 2 PD5/A5/UTX/T2CH4_/URX_ (io), 3 PD6/A6/URX/T2CH3_/UTX_ (io), 4 PD7/NRST/T2CH4/OPP1/UCK_ (io), 5 PA1/OSCI/A1/T1CH2/OPN0 (io), 6 PA2/OSCO/A0/T1CH2N/OPP0/AETR2_ (io), 7 VSS (power), 8 PD0/T1CH1N/OPN1/SDA_/UTX_ (io), 9 VDD (power), 10 PC0/T2CH3/UTX_/NSS_/T1CH3_ (io), 11 PC1/SDA/NSS/T2CH4_/T2CH1ETR_/T1BKIN_/URX_ (io), 12 PC2/SCL/URTS/T1BKIN/AETR_/T2CH2_/T1ETR_ (io), 13 PC3/T1CH3/T1CH1N_/UCTS_ (io), 14 PC4/A2/T1CH4/MCO/T1CH1CH2N_ (io), 15 PC5/SCK/T1ETR/T2CH1ETR_/SCL_/UCK_/T1CH3_ (io), 16 PC6/MOSI/T1CH1CH3N_/UCTS_/SDA_ (io), 17 PC7/MISO/T1CH2_/T2CH2_/URTS_ (io), 18 PD1/SWIO/AETR2/T1CH3N/SCL_/URX_ (io), 19 PD2/A3/T1CH1/T2CH3_/T1CH2N_ (io), 20 PD3/A4/T2CH2/AETR/UCTS/T1CH4_ (io)

## CH32V003F4U6
designator U?
RISC-V MCU, 48MHz
footprint QFN20_3X3
pins: 0 VSS (power), 1 (io), 2 (io), 3 (io), 4 VSS (power), 5 (io), 6 VDD (power), 7 (io), 8 (io), 9 (io), 10 (io), 11 (io), 12 (io), 13 (io), 14 (io), 15 (io), 16 (io), 17 (io), 18 (io), 19 (io), 20 (io)

## CH32V003J4M6
designator U?
RISC-V MCU, 48MHz
footprint SOP8
pins: 1 (io), 2 VSS (power), 3 PA2/OSCO/A0/T1CH2N/OPP0/AETR2_ (io), 4 VDD (power), 5 PC1/SDA/NSS/T2CH4_/T2CH1ETR_/T1BKIN_/URX_ (io), 6 (io), 7 PC4/A2/T1CH4/MCO/T1CH1CH2N_ (io), 8 (io)

## CH32V004F6P1
designator U?
RISC-V MCU, 48MHz, ADC/UART/I2C/SPI
footprint TSSOP20
pins: 1 PD4/T1C4_/T2C1/A7 (io), 2 PD5/T2C4_/TX/RX_/A5 (io), 3 PD6/T2C3_/RX/TX_/A6 (io), 4 PD7/RST/T2C4/PA4 (io), 5 PA1/T1C2/XI/A1 (io), 6 PA2/T1C2N/AET2_/XO/A0 (io), 7 VSS (power), 8 PD0/T1C1N/SDA_/TX_ (io), 9 VDD (power), 10 PC0/T1C3_/T2C3/NSS_/TX_ (io), 11 PC1/T1BK_/T2C1_/T2C4_/RX_/SDA/NSS (io), 12 PC2/T1BK/T2C2_/SCL/AET_ (io), 13 PC3/T1C3/T1C1N_ (io), 14 PC4/T1C4/T1C1_/T1C2N_/MCO/A2 (io), 15 PC5/T1E/T1C3_/T2C1_/SCL_/SCK (io), 16 PC6/T1C1_/T1C3N_/SDA_/MOSI (io), 17 PC7/T1C2_/T2C2_/MISO (io), 18 PD1/SWIO/T1C3N/SCL_/RX_/AET2 (io), 19 PD2/T1C1/T1C2N_/T2C3_/A3 (io), 20 PD3/T1C4_/T2C2/AET/A4 (io)

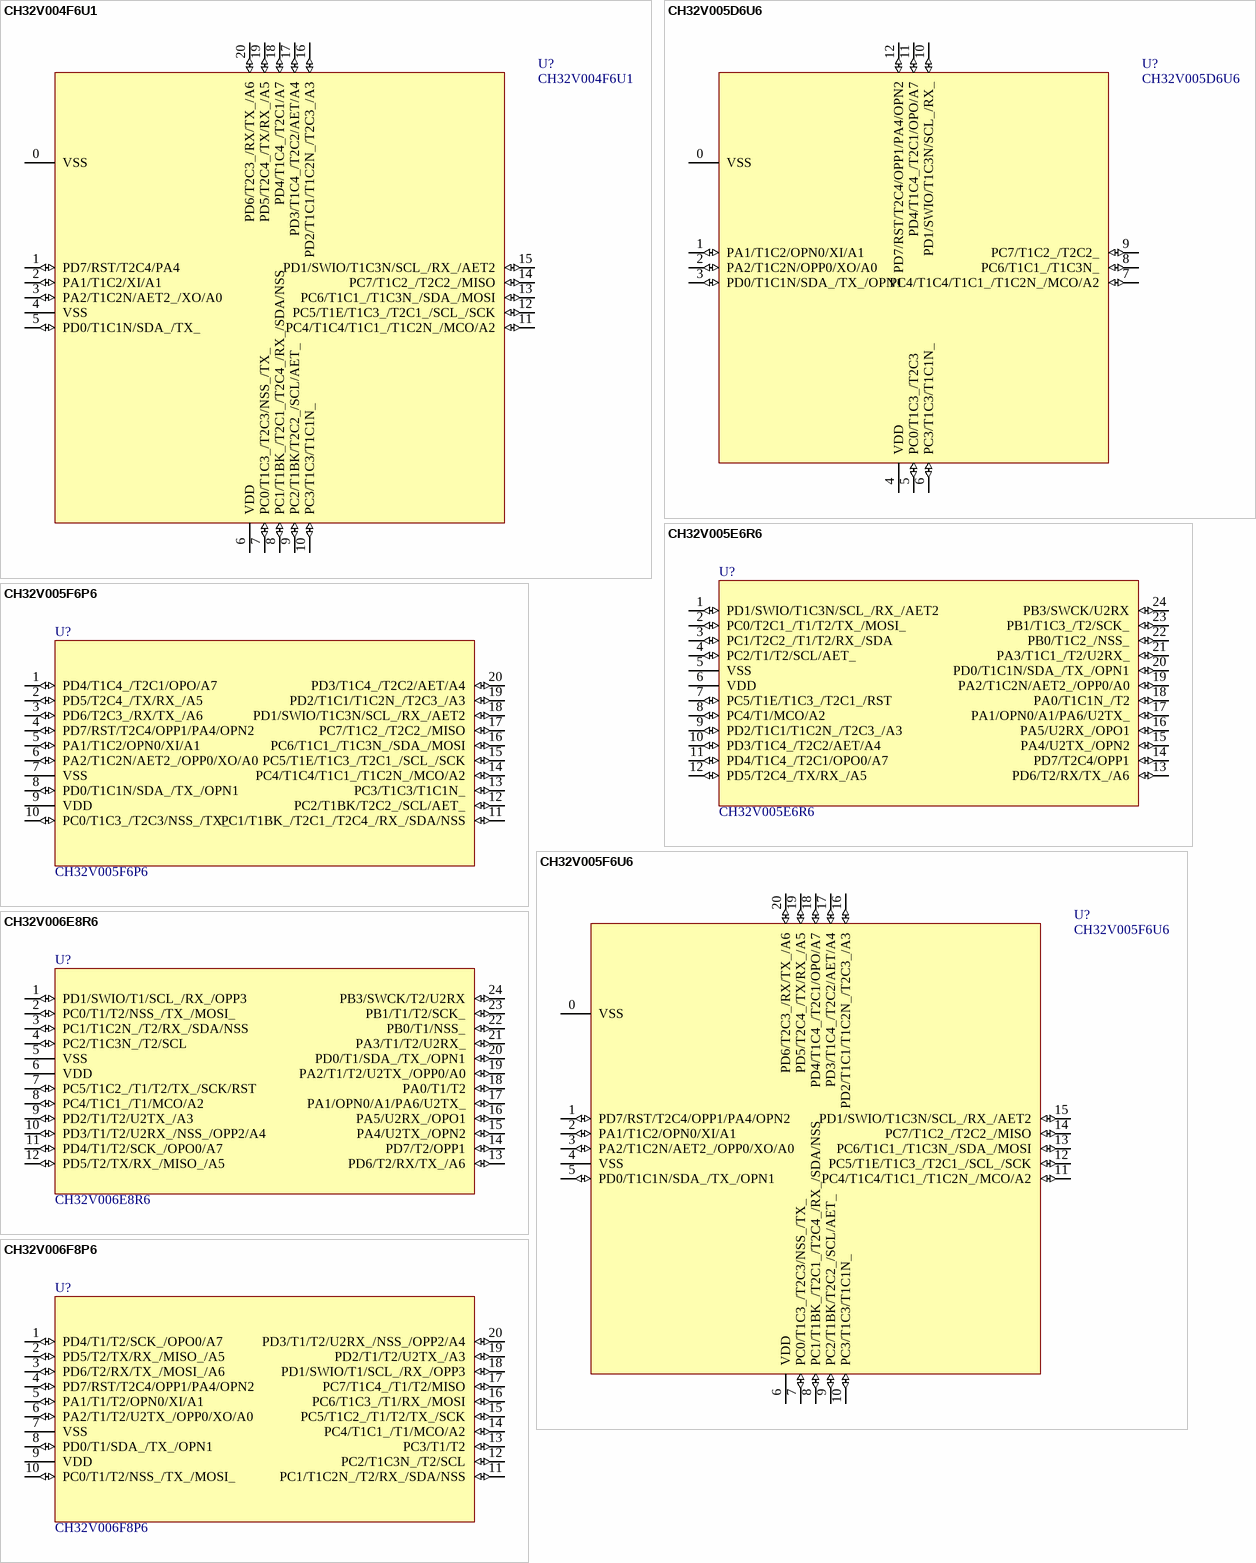
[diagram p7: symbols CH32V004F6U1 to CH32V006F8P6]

## CH32V004F6U1
designator U?
RISC-V MCU, 48MHz, ADC/UART/I2C/SPI
footprint QFN20_3X3
pins: 0 VSS (power), 1 PD7/RST/T2C4/PA4 (io), 2 PA1/T1C2/XI/A1 (io), 3 PA2/T1C2N/AET2_/XO/A0 (io), 4 VSS (power), 5 PD0/T1C1N/SDA_/TX_ (io), 6 VDD (power), 7 PC0/T1C3_/T2C3/NSS_/TX_ (io), 8 PC1/T1BK_/T2C1_/T2C4_/RX_/SDA/NSS (io), 9 PC2/T1BK/T2C2_/SCL/AET_ (io), 10 PC3/T1C3/T1C1N_ (io), 11 PC4/T1C4/T1C1_/T1C2N_/MCO/A2 (io), 12 PC5/T1E/T1C3_/T2C1_/SCL_/SCK (io), 13 PC6/T1C1_/T1C3N_/SDA_/MOSI (io), 14 PC7/T1C2_/T2C2_/MISO (io), 15 PD1/SWIO/T1C3N/SCL_/RX_/AET2 (io), 16 PD2/T1C1/T1C2N_/T2C3_/A3 (io), 17 PD3/T1C4_/T2C2/AET/A4 (io), 18 PD4/T1C4_/T2C1/A7 (io), 19 PD5/T2C4_/TX/RX_/A5 (io), 20 PD6/T2C3_/RX/TX_/A6 (io)

## CH32V005D6U6
designator U?
RISC-V MCU, 48MHz, ADC/OPA/2*UART/I2C
footprint QFN12_2X2
pins: 0 VSS (power), 1 PA1/T1C2/OPN0/XI/A1 (io), 2 PA2/T1C2N/OPP0/XO/A0 (io), 3 PD0/T1C1N/SDA_/TX_/OPN1 (io), 4 VDD (power), 5 PC0/T1C3_/T2C3 (io), 6 PC3/T1C3/T1C1N_ (io), 7 PC4/T1C4/T1C1_/T1C2N_/MCO/A2 (io), 8 PC6/T1C1_/T1C3N_ (io), 9 PC7/T1C2_/T2C2_ (io), 10 PD1/SWIO/T1C3N/SCL_/RX_ (io), 11 PD4/T1C4_/T2C1/OPO/A7 (io), 12 PD7/RST/T2C4/OPP1/PA4/OPN2 (io)

## CH32V005E6R6
designator U?
RISC-V MCU, 48MHz, ADC/OPA/CMP/2*UART/I2C/SPI
footprint QSOP24
pins: 1 PD1/SWIO/T1C3N/SCL_/RX_/AET2 (io), 2 PC0/T2C1_/T1/T2/TX_/MOSI_ (io), 3 PC1/T2C2_/T1/T2/RX_/SDA (io), 4 PC2/T1/T2/SCL/AET_ (io), 5 VSS (power), 6 VDD (power), 7 PC5/T1E/T1C3_/T2C1_/RST (io), 8 PC4/T1/MCO/A2 (io), 9 PD2/T1C1/T1C2N_/T2C3_/A3 (io), 10 PD3/T1C4_/T2C2/AET/A4 (io), 11 PD4/T1C4_/T2C1/OPO0/A7 (io), 12 PD5/T2C4_/TX/RX_/A5 (io), 13 PD6/T2/RX/TX_/A6 (io), 14 PD7/T2C4/OPP1 (io), 15 PA4/U2TX_/OPN2 (io), 16 PA5/U2RX_/OPO1 (io), 17 PA1/OPN0/A1/PA6/U2TX_ (io), 18 PA0/T1C1N_/T2 (io), 19 PA2/T1C2N/AET2_/OPP0/A0 (io), 20 PD0/T1C1N/SDA_/TX_/OPN1 (io), 21 PA3/T1C1_/T2/U2RX_ (io), 22 PB0/T1C2_/NSS_ (io), 23 PB1/T1C3_/T2/SCK_ (io), 24 PB3/SWCK/U2RX (io)

## CH32V005F6P6
designator U?
RISC-V MCU, 48MHz, ADC/OPA/2*UART/I2C/SPI
footprint TSSOP20
pins: 1 PD4/T1C4_/T2C1/OPO/A7 (io), 2 PD5/T2C4_/TX/RX_/A5 (io), 3 PD6/T2C3_/RX/TX_/A6 (io), 4 PD7/RST/T2C4/OPP1/PA4/OPN2 (io), 5 PA1/T1C2/OPN0/XI/A1 (io), 6 PA2/T1C2N/AET2_/OPP0/XO/A0 (io), 7 VSS (power), 8 PD0/T1C1N/SDA_/TX_/OPN1 (io), 9 VDD (power), 10 PC0/T1C3_/T2C3/NSS_/TX_ (io), 11 PC1/T1BK_/T2C1_/T2C4_/RX_/SDA/NSS (io), 12 PC2/T1BK/T2C2_/SCL/AET_ (io), 13 PC3/T1C3/T1C1N_ (io), 14 PC4/T1C4/T1C1_/T1C2N_/MCO/A2 (io), 15 PC5/T1E/T1C3_/T2C1_/SCL_/SCK (io), 16 PC6/T1C1_/T1C3N_/SDA_/MOSI (io), 17 PC7/T1C2_/T2C2_/MISO (io), 18 PD1/SWIO/T1C3N/SCL_/RX_/AET2 (io), 19 PD2/T1C1/T1C2N_/T2C3_/A3 (io), 20 PD3/T1C4_/T2C2/AET/A4 (io)

## CH32V005F6U6
designator U?
RISC-V MCU, 48MHz, ADC/OPA/2*UART/I2C/SPI
footprint QFN20_3X3
pins: 0 VSS (power), 1 PD7/RST/T2C4/OPP1/PA4/OPN2 (io), 2 PA1/T1C2/OPN0/XI/A1 (io), 3 PA2/T1C2N/AET2_/OPP0/XO/A0 (io), 4 VSS (power), 5 PD0/T1C1N/SDA_/TX_/OPN1 (io), 6 VDD (power), 7 PC0/T1C3_/T2C3/NSS_/TX_ (io), 8 PC1/T1BK_/T2C1_/T2C4_/RX_/SDA/NSS (io), 9 PC2/T1BK/T2C2_/SCL/AET_ (io), 10 PC3/T1C3/T1C1N_ (io), 11 PC4/T1C4/T1C1_/T1C2N_/MCO/A2 (io), 12 PC5/T1E/T1C3_/T2C1_/SCL_/SCK (io), 13 PC6/T1C1_/T1C3N_/SDA_/MOSI (io), 14 PC7/T1C2_/T2C2_/MISO (io), 15 PD1/SWIO/T1C3N/SCL_/RX_/AET2 (io), 16 PD2/T1C1/T1C2N_/T2C3_/A3 (io), 17 PD3/T1C4_/T2C2/AET/A4 (io), 18 PD4/T1C4_/T2C1/OPO/A7 (io), 19 PD5/T2C4_/TX/RX_/A5 (io), 20 PD6/T2C3_/RX/TX_/A6 (io)

## CH32V006E8R6
designator U?
RISC-V MCU, 48MHz, ADC/OPA/CMP/2*UART/I2C/SPI
footprint QSOP24
pins: 1 PD1/SWIO/T1/SCL_/RX_/OPP3 (io), 2 PC0/T1/T2/NSS_/TX_/MOSI_ (io), 3 PC1/T1C2N_/T2/RX_/SDA/NSS (io), 4 PC2/T1C3N_/T2/SCL (io), 5 VSS (power), 6 VDD (power), 7 PC5/T1C2_/T1/T2/TX_/SCK/RST (io), 8 PC4/T1C1_/T1/MCO/A2 (io), 9 PD2/T1/T2/U2TX_/A3 (io), 10 PD3/T1/T2/U2RX_/NSS_/OPP2/A4 (io), 11 PD4/T1/T2/SCK_/OPO0/A7 (io), 12 PD5/T2/TX/RX_/MISO_/A5 (io), 13 PD6/T2/RX/TX_/A6 (io), 14 PD7/T2/OPP1 (io), 15 PA4/U2TX_/OPN2 (io), 16 PA5/U2RX_/OPO1 (io), 17 PA1/OPN0/A1/PA6/U2TX_ (io), 18 PA0/T1/T2 (io), 19 PA2/T1/T2/U2TX_/OPP0/A0 (io), 20 PD0/T1/SDA_/TX_/OPN1 (io), 21 PA3/T1/T2/U2RX_ (io), 22 PB0/T1/NSS_ (io), 23 PB1/T1/T2/SCK_ (io), 24 PB3/SWCK/T2/U2RX (io)

## CH32V006F8P6
designator U?
RISC-V MCU, 48MHz, ADC/OPA/2*UART/I2C/SPI
footprint TSSOP20
pins: 1 PD4/T1/T2/SCK_/OPO0/A7 (io), 2 PD5/T2/TX/RX_/MISO_/A5 (io), 3 PD6/T2/RX/TX_/MOSI_/A6 (io), 4 PD7/RST/T2C4/OPP1/PA4/OPN2 (io), 5 PA1/T1/T2/OPN0/XI/A1 (io), 6 PA2/T1/T2/U2TX_/OPP0/XO/A0 (io), 7 VSS (power), 8 PD0/T1/SDA_/TX_/OPN1 (io), 9 VDD (power), 10 PC0/T1/T2/NSS_/TX_/MOSI_ (io), 11 PC1/T1C2N_/T2/RX_/SDA/NSS (io), 12 PC2/T1C3N_/T2/SCL (io), 13 PC3/T1/T2 (io), 14 PC4/T1C1_/T1/MCO/A2 (io), 15 PC5/T1C2_/T1/T2/TX_/SCK (io), 16 PC6/T1C3_/T1/RX_/MOSI (io), 17 PC7/T1C4_/T1/T2/MISO (io), 18 PD1/SWIO/T1/SCL_/RX_/OPP3 (io), 19 PD2/T1/T2/U2TX_/A3 (io), 20 PD3/T1/T2/U2RX_/NSS_/OPP2/A4 (io)

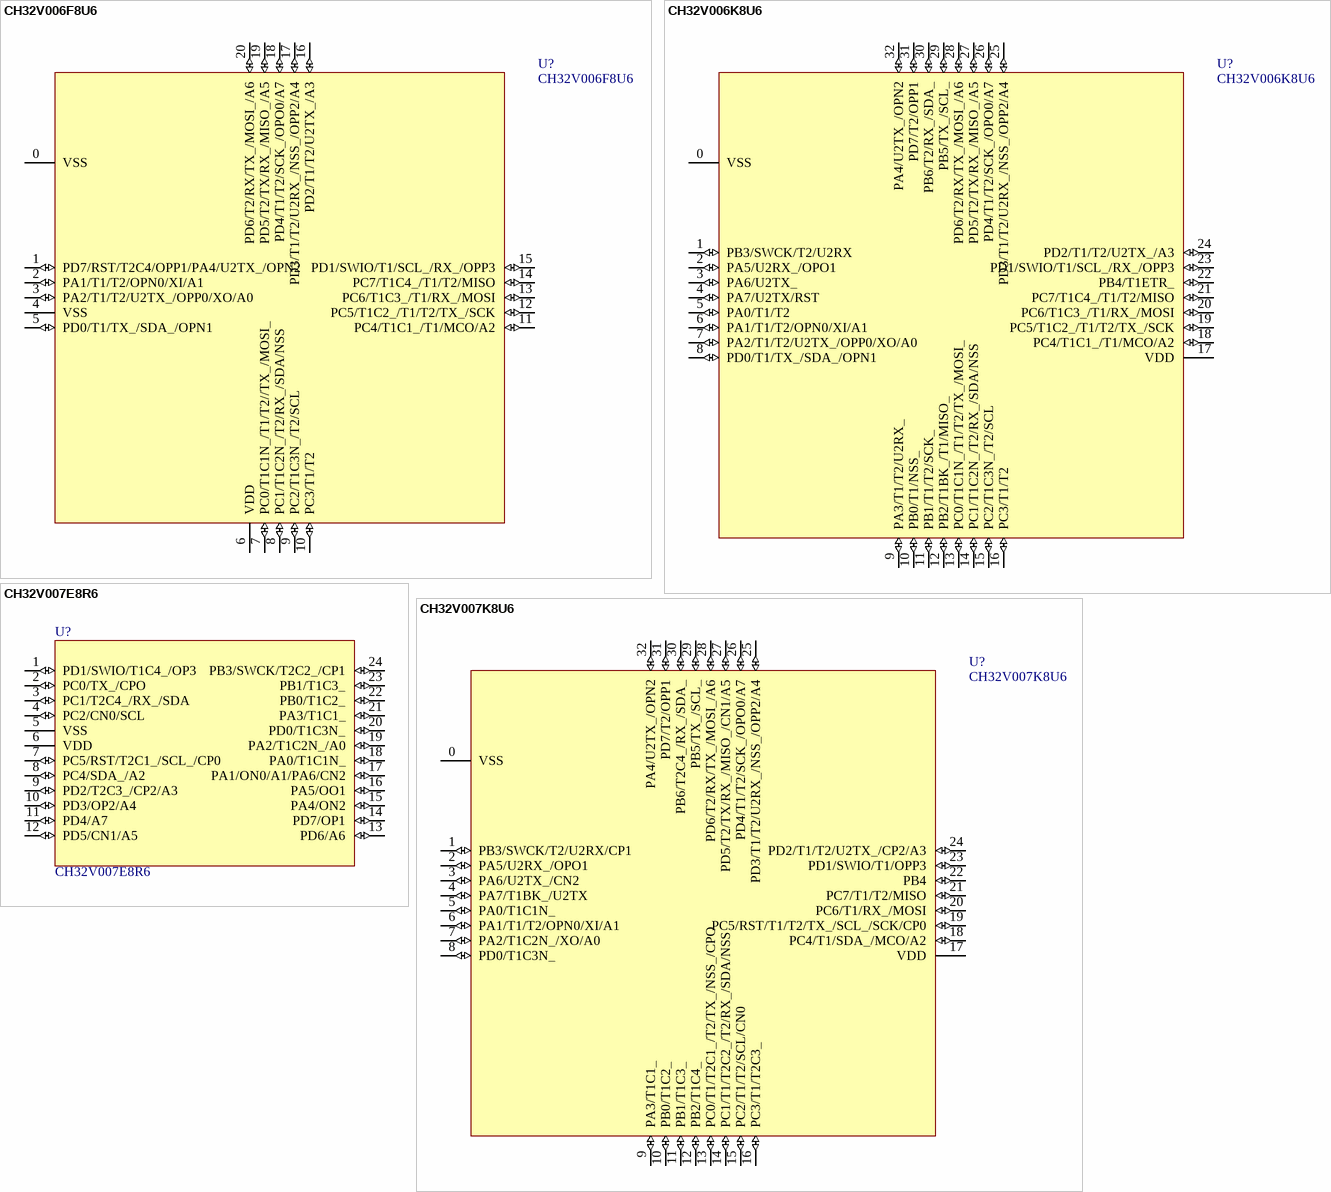
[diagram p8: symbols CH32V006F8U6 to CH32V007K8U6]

## CH32V006F8U6
designator U?
RISC-V MCU, 48MHz, ADC/OPA/2*UART/I2C/SPI
footprint QFN20_3X3
pins: 0 VSS (power), 1 PD7/RST/T2C4/OPP1/PA4/U2TX_/OPN2 (io), 2 PA1/T1/T2/OPN0/XI/A1 (io), 3 PA2/T1/T2/U2TX_/OPP0/XO/A0 (io), 4 VSS (power), 5 PD0/T1/TX_/SDA_/OPN1 (io), 6 VDD (power), 7 PC0/T1C1N_/T1/T2//TX_/MOSI_ (io), 8 PC1/T1C2N_/T2/RX_/SDA/NSS (io), 9 PC2/T1C3N_/T2/SCL (io), 10 PC3/T1/T2 (io), 11 PC4/T1C1_/T1/MCO/A2 (io), 12 PC5/T1C2_/T1/T2/TX_/SCK (io), 13 PC6/T1C3_/T1/RX_/MOSI (io), 14 PC7/T1C4_/T1/T2/MISO (io), 15 PD1/SWIO/T1/SCL_/RX_/OPP3 (io), 16 PD2/T1/T2/U2TX_/A3 (io), 17 PD3/T1/T2/U2RX_/NSS_/OPP2/A4 (io), 18 PD4/T1/T2/SCK_/OPO0/A7 (io), 19 PD5/T2/TX/RX_/MISO_/A5 (io), 20 PD6/T2/RX/TX_/MOSI_/A6 (io)

## CH32V006K8U6
designator U?
RISC-V MCU, 48MHz, ADC/OPA/2*UART/I2C/SPI
footprint QFN32_4X4
pins: 0 VSS (power), 1 PB3/SWCK/T2/U2RX (io), 2 PA5/U2RX_/OPO1 (io), 3 PA6/U2TX_ (io), 4 PA7/U2TX/RST (io), 5 PA0/T1/T2 (io), 6 PA1/T1/T2/OPN0/XI/A1 (io), 7 PA2/T1/T2/U2TX_/OPP0/XO/A0 (io), 8 PD0/T1/TX_/SDA_/OPN1 (io), 9 PA3/T1/T2/U2RX_ (io), 10 PB0/T1/NSS_ (io), 11 PB1/T1/T2/SCK_ (io), 12 PB2/T1BK_/T1/MISO_ (io), 13 PC0/T1C1N_/T1/T2/TX_/MOSI_ (io), 14 PC1/T1C2N_/T2/RX_/SDA/NSS (io), 15 PC2/T1C3N_/T2/SCL (io), 16 PC3/T1/T2 (io), 17 VDD (power), 18 PC4/T1C1_/T1/MCO/A2 (io), 19 PC5/T1C2_/T1/T2/TX_/SCK (io), 20 PC6/T1C3_/T1/RX_/MOSI (io), 21 PC7/T1C4_/T1/T2/MISO (io), 22 PB4/T1ETR_ (io), 23 PD1/SWIO/T1/SCL_/RX_/OPP3 (io), 24 PD2/T1/T2/U2TX_/A3 (io), 25 PD3/T1/T2/U2RX_/NSS_/OPP2/A4 (io), 26 PD4/T1/T2/SCK_/OPO0/A7 (io), 27 PD5/T2/TX/RX_/MISO_/A5 (io), 28 PD6/T2/RX/TX_/MOSI_/A6 (io), 29 PB5/TX_/SCL_ (io), 30 PB6/T2/RX_/SDA_ (io), 31 PD7/T2/OPP1 (io), 32 PA4/U2TX_/OPN2 (io)

## CH32V007E8R6
designator U?
RISC-V MCU, ADC/OPA/CMP/2*UART/I2C/SPI
footprint QSOP24
pins: 1 PD1/SWIO/T1C4_/OP3 (io), 2 PC0/TX_/CPO (io), 3 PC1/T2C4_/RX_/SDA (io), 4 PC2/CN0/SCL (io), 5 VSS (power), 6 VDD (power), 7 PC5/RST/T2C1_/SCL_/CP0 (io), 8 PC4/SDA_/A2 (io), 9 PD2/T2C3_/CP2/A3 (io), 10 PD3/OP2/A4 (io), 11 PD4/A7 (io), 12 PD5/CN1/A5 (io), 13 PD6/A6 (io), 14 PD7/OP1 (io), 15 PA4/ON2 (io), 16 PA5/OO1 (io), 17 PA1/ON0/A1/PA6/CN2 (io), 18 PA0/T1C1N_ (io), 19 PA2/T1C2N_/A0 (io), 20 PD0/T1C3N_ (io), 21 PA3/T1C1_ (io), 22 PB0/T1C2_ (io), 23 PB1/T1C3_ (io), 24 PB3/SWCK/T2C2_/CP1 (io)

## CH32V007K8U6
designator U?
RISC-V MCU, ADC/OPA/CMP/2*UART/I2C/SPI
footprint QFN32_4X4
pins: 0 VSS (power), 1 PB3/SWCK/T2/U2RX/CP1 (io), 2 PA5/U2RX_/OPO1 (io), 3 PA6/U2TX_/CN2 (io), 4 PA7/T1BK_/U2TX (io), 5 PA0/T1C1N_ (io), 6 PA1/T1/T2/OPN0/XI/A1 (io), 7 PA2/T1C2N_/XO/A0 (io), 8 PD0/T1C3N_ (io), 9 PA3/T1C1_ (io), 10 PB0/T1C2_ (io), 11 PB1/T1C3_ (io), 12 PB2/T1C4_ (io), 13 PC0/T1/T2C1_/T2/TX_/NSS_/CPO (io), 14 PC1/T1/T2C2_/T2/RX_/SDA/NSS (io), 15 PC2/T1/T2/SCL/CN0 (io), 16 PC3/T1/T2C3_ (io), 17 VDD (power), 18 PC4/T1/SDA_/MCO/A2 (io), 19 PC5/RST/T1/T2/TX_/SCL_/SCK/CP0 (io), 20 PC6/T1/RX_/MOSI (io), 21 PC7/T1/T2/MISO (io), 22 PB4 (io), 23 PD1/SWIO/T1/OPP3 (io), 24 PD2/T1/T2/U2TX_/CP2/A3 (io), 25 PD3/T1/T2/U2RX_/NSS_/OPP2/A4 (io), 26 PD4/T1/T2/SCK_/OPO0/A7 (io), 27 PD5/T2/TX/RX_/MISO_/CN1/A5 (io), 28 PD6/T2/RX/TX_/MOSI_/A6 (io), 29 PB5/TX_/SCL_ (io), 30 PB6/T2C4_/RX_/SDA_ (io), 31 PD7/T2/OPP1 (io), 32 PA4/U2TX_/OPN2 (io)

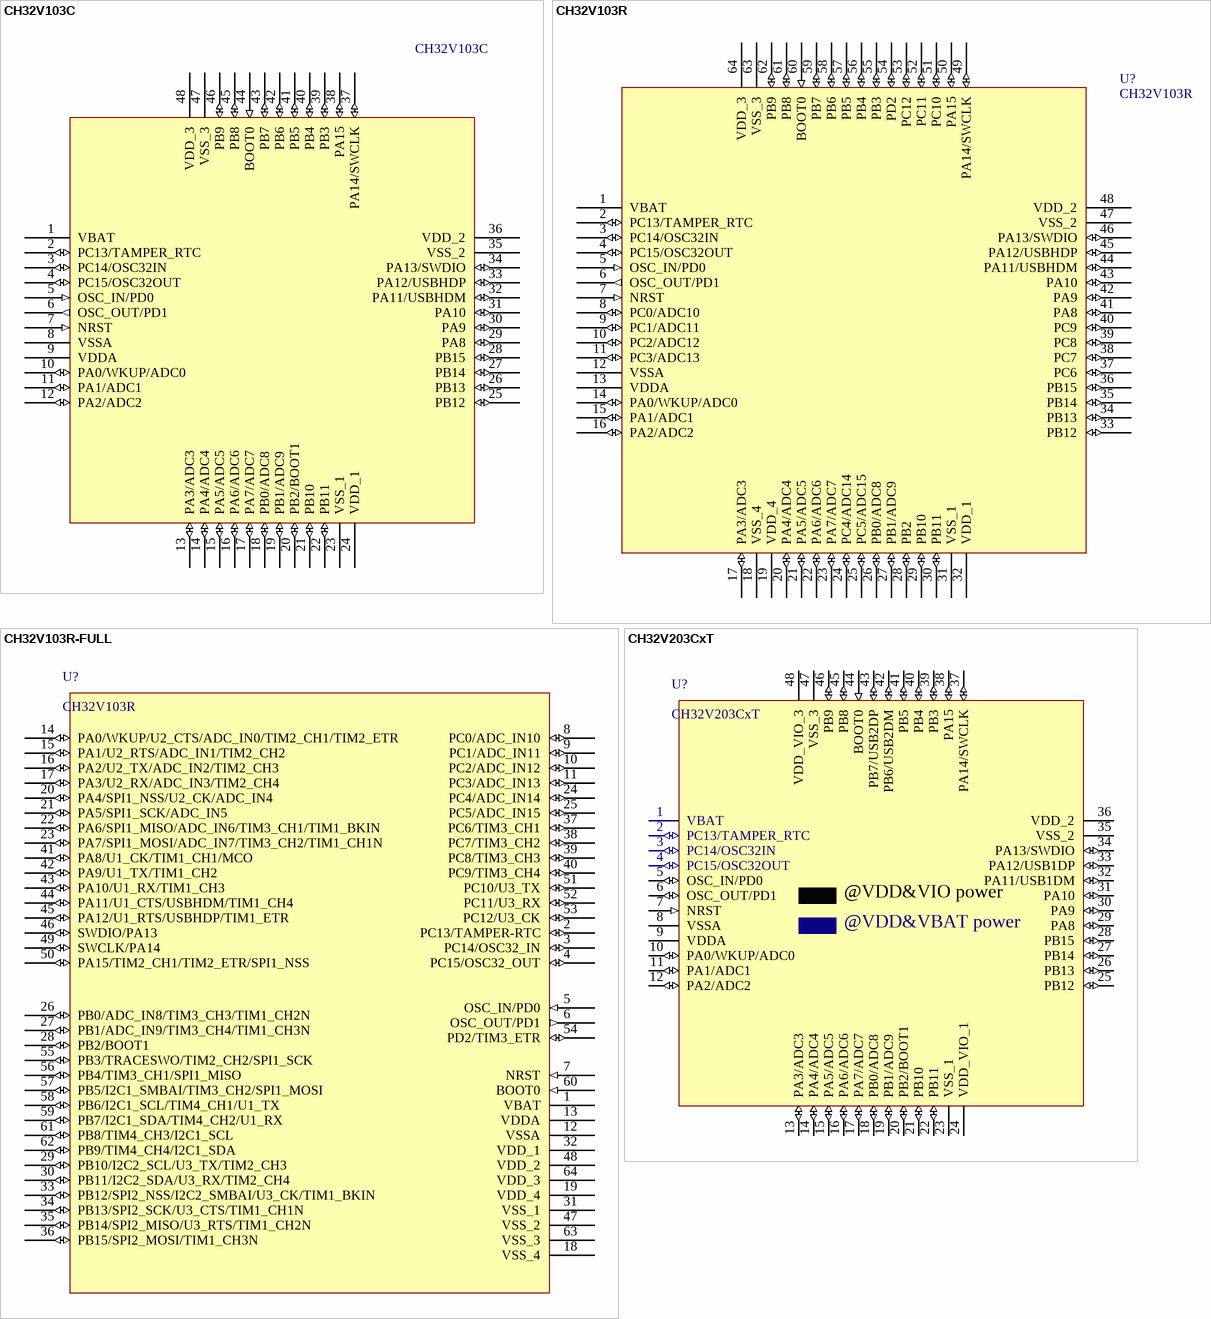
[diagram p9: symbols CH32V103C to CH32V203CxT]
